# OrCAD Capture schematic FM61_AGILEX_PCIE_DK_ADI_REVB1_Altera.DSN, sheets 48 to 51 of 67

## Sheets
48 Power Inputs: size Custom
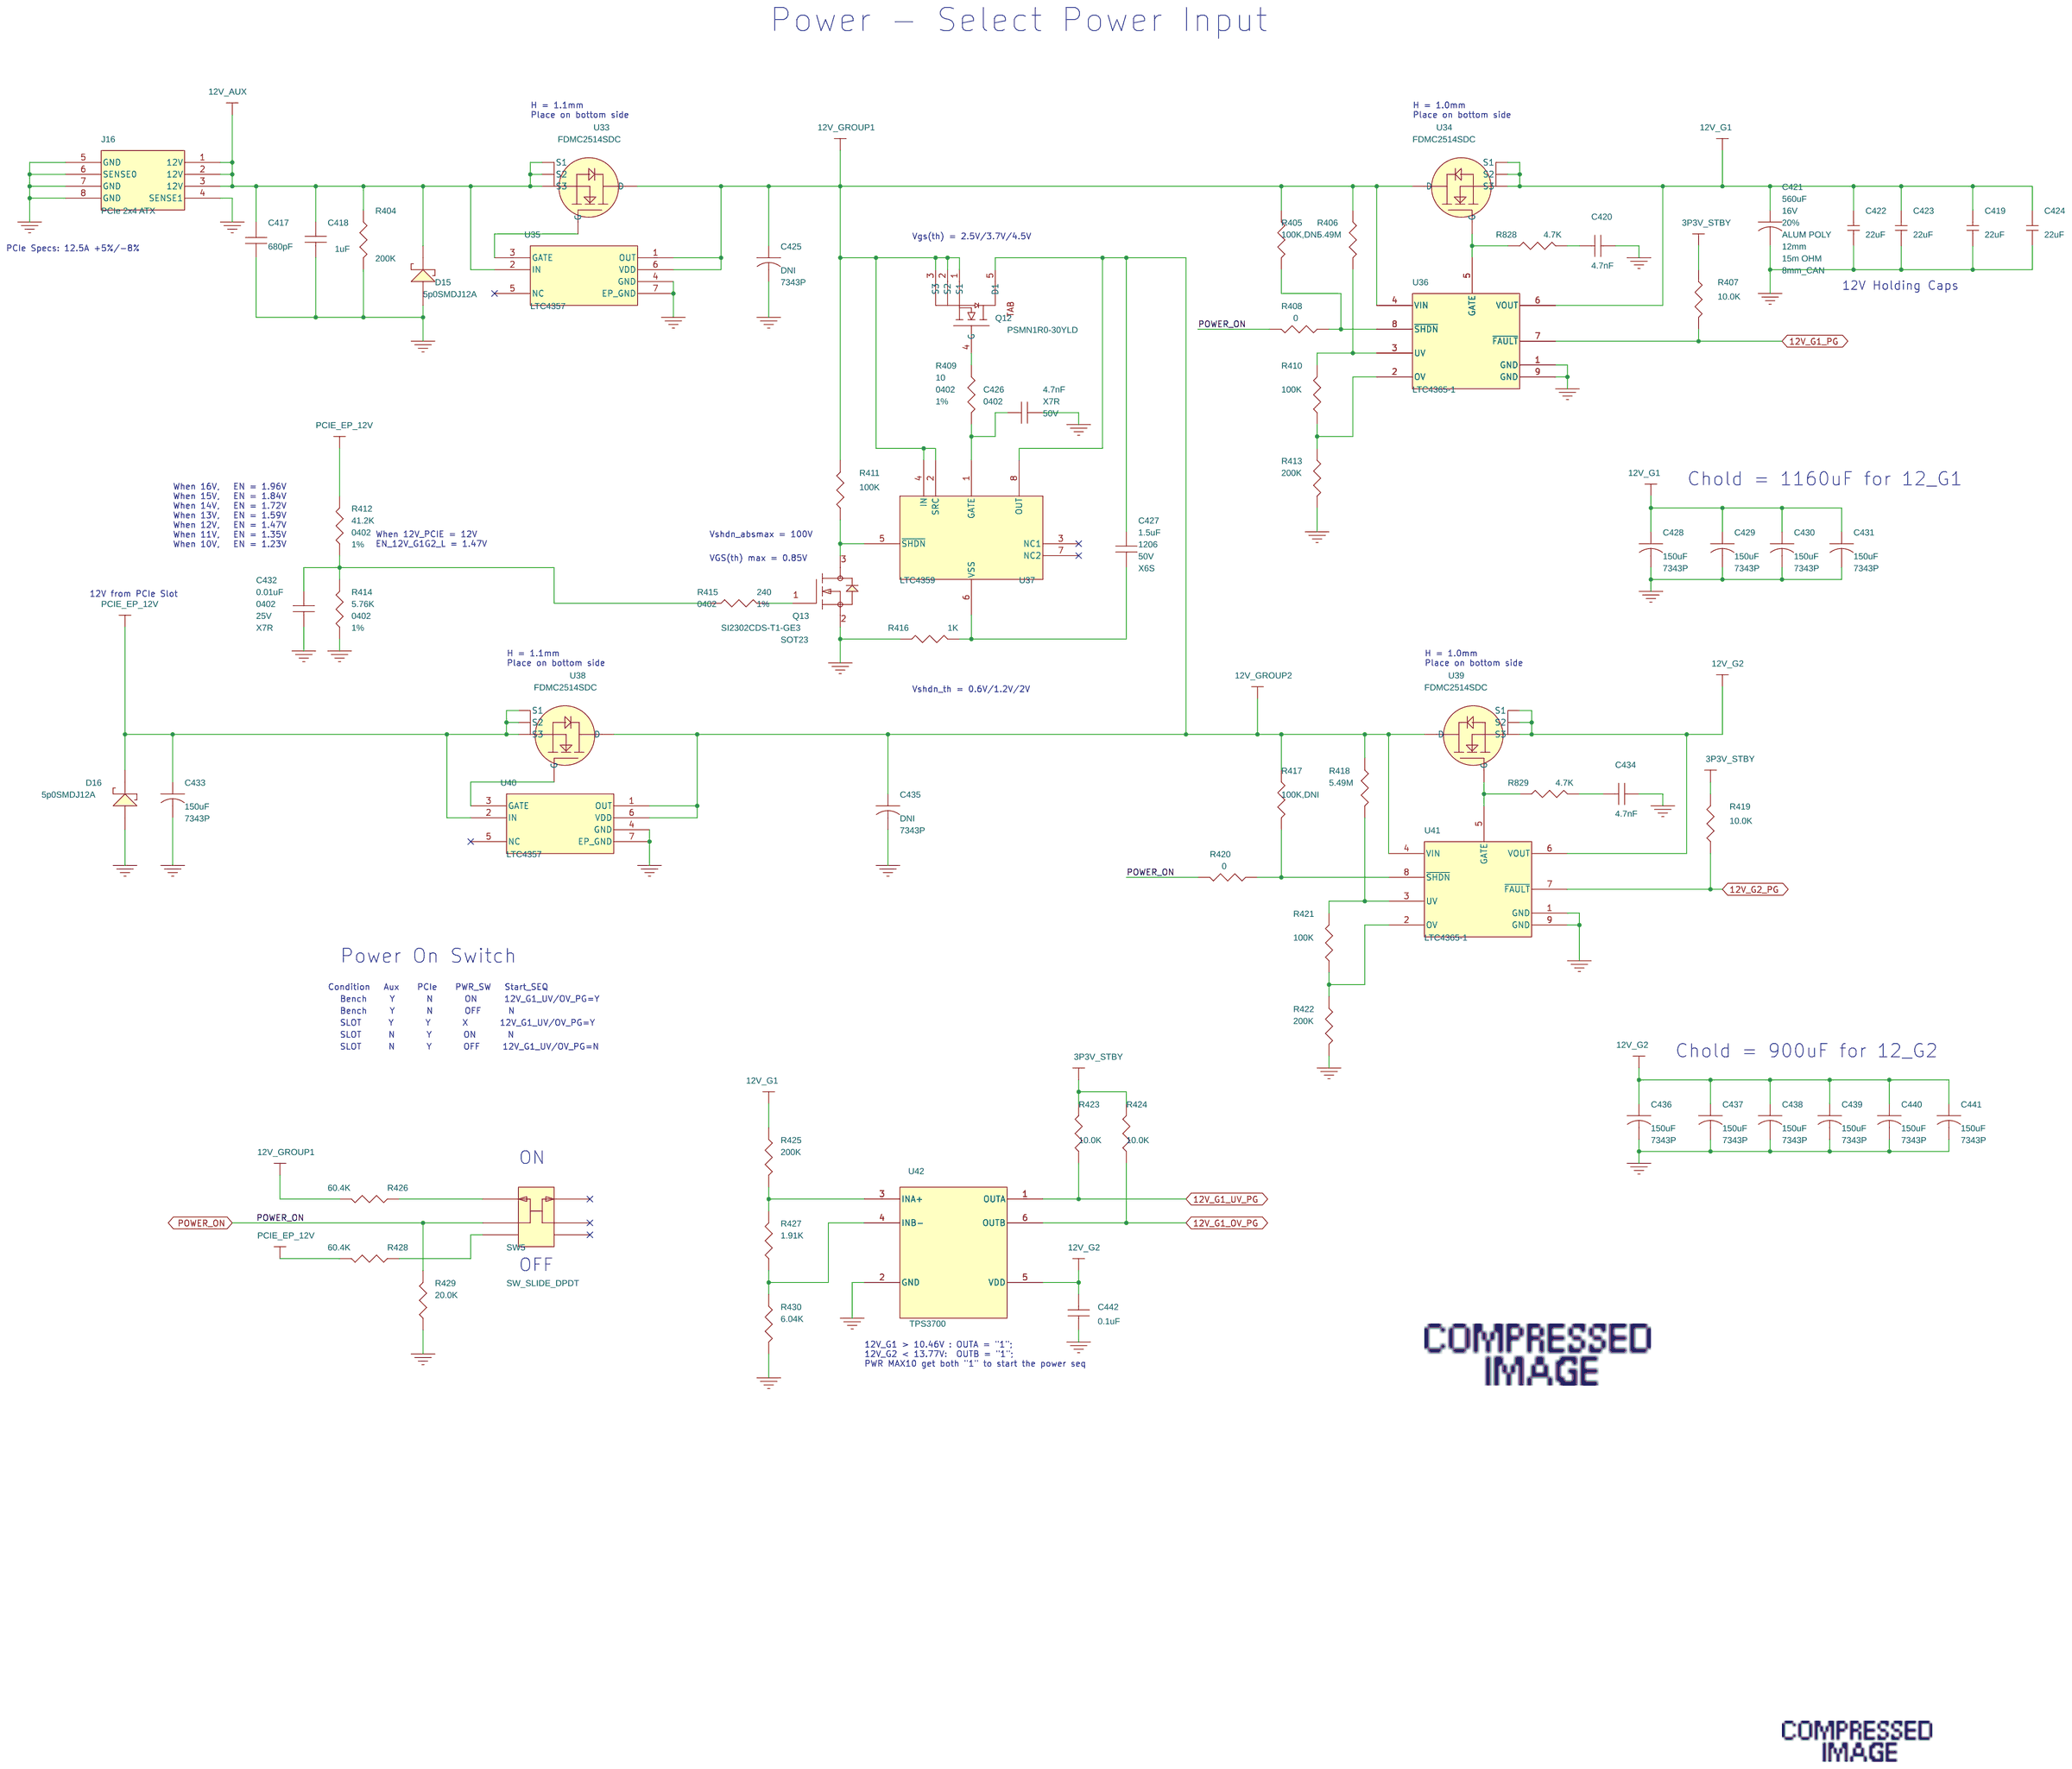
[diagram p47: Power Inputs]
49 PWR - 12V to 5V: size B
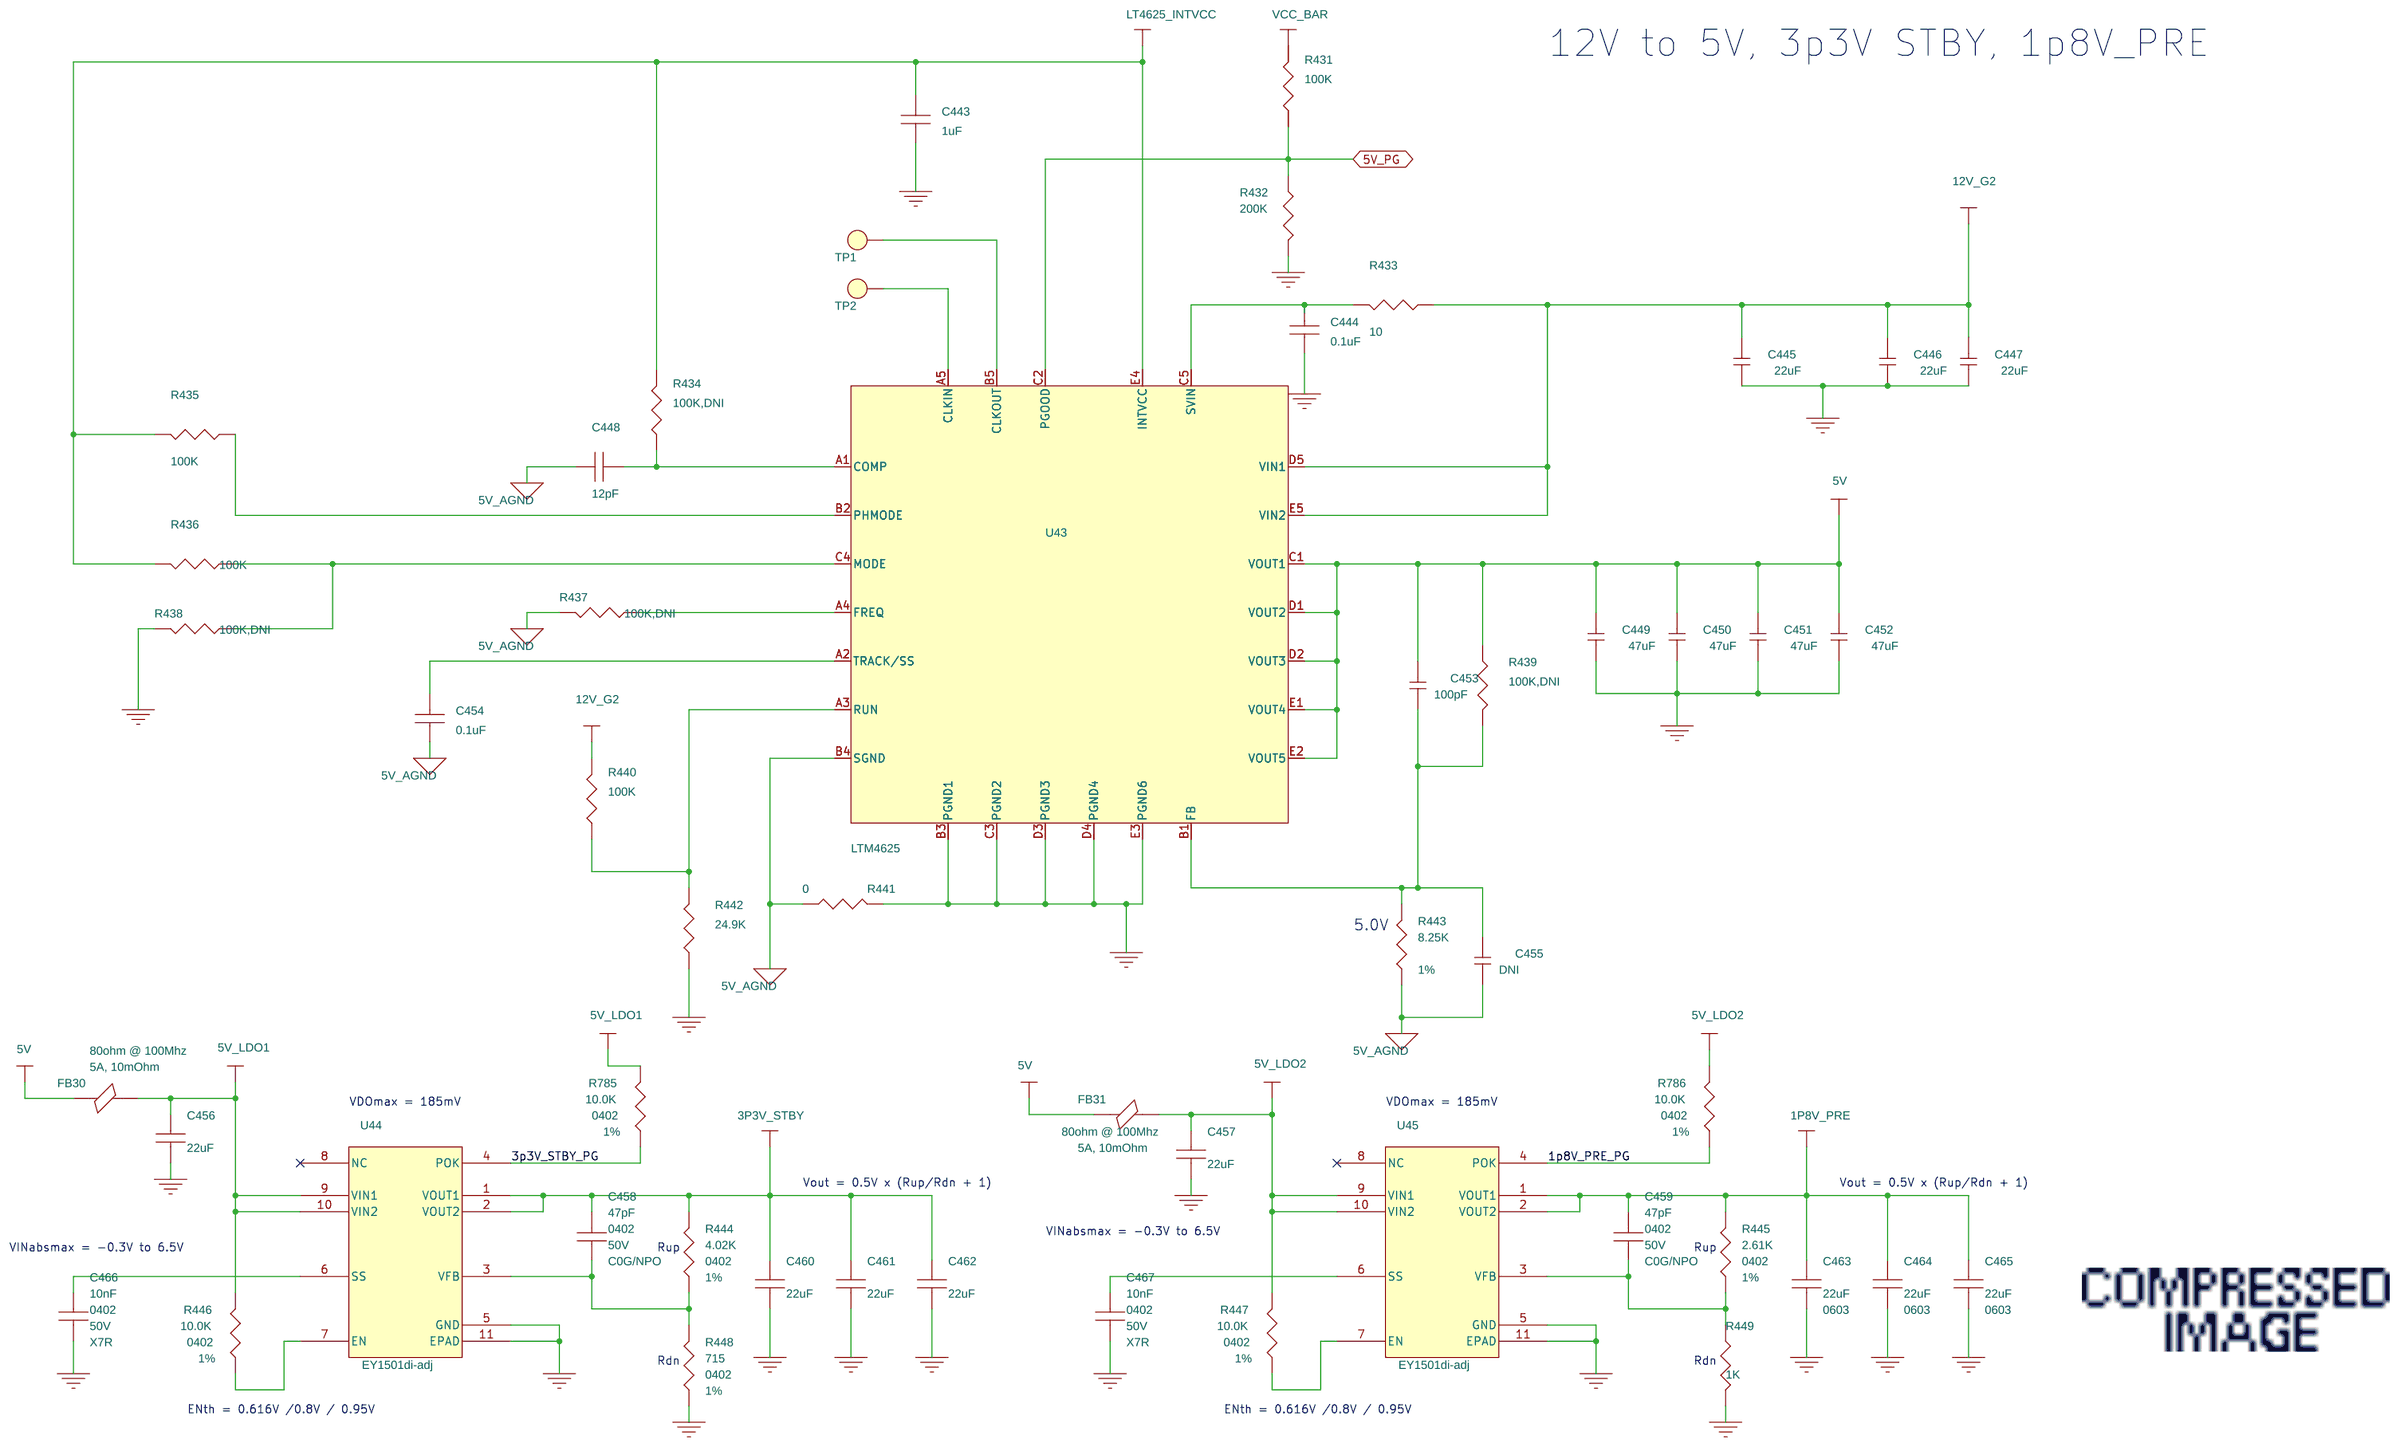
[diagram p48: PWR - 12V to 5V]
50 PWR - 12V to 3.3V: size Custom
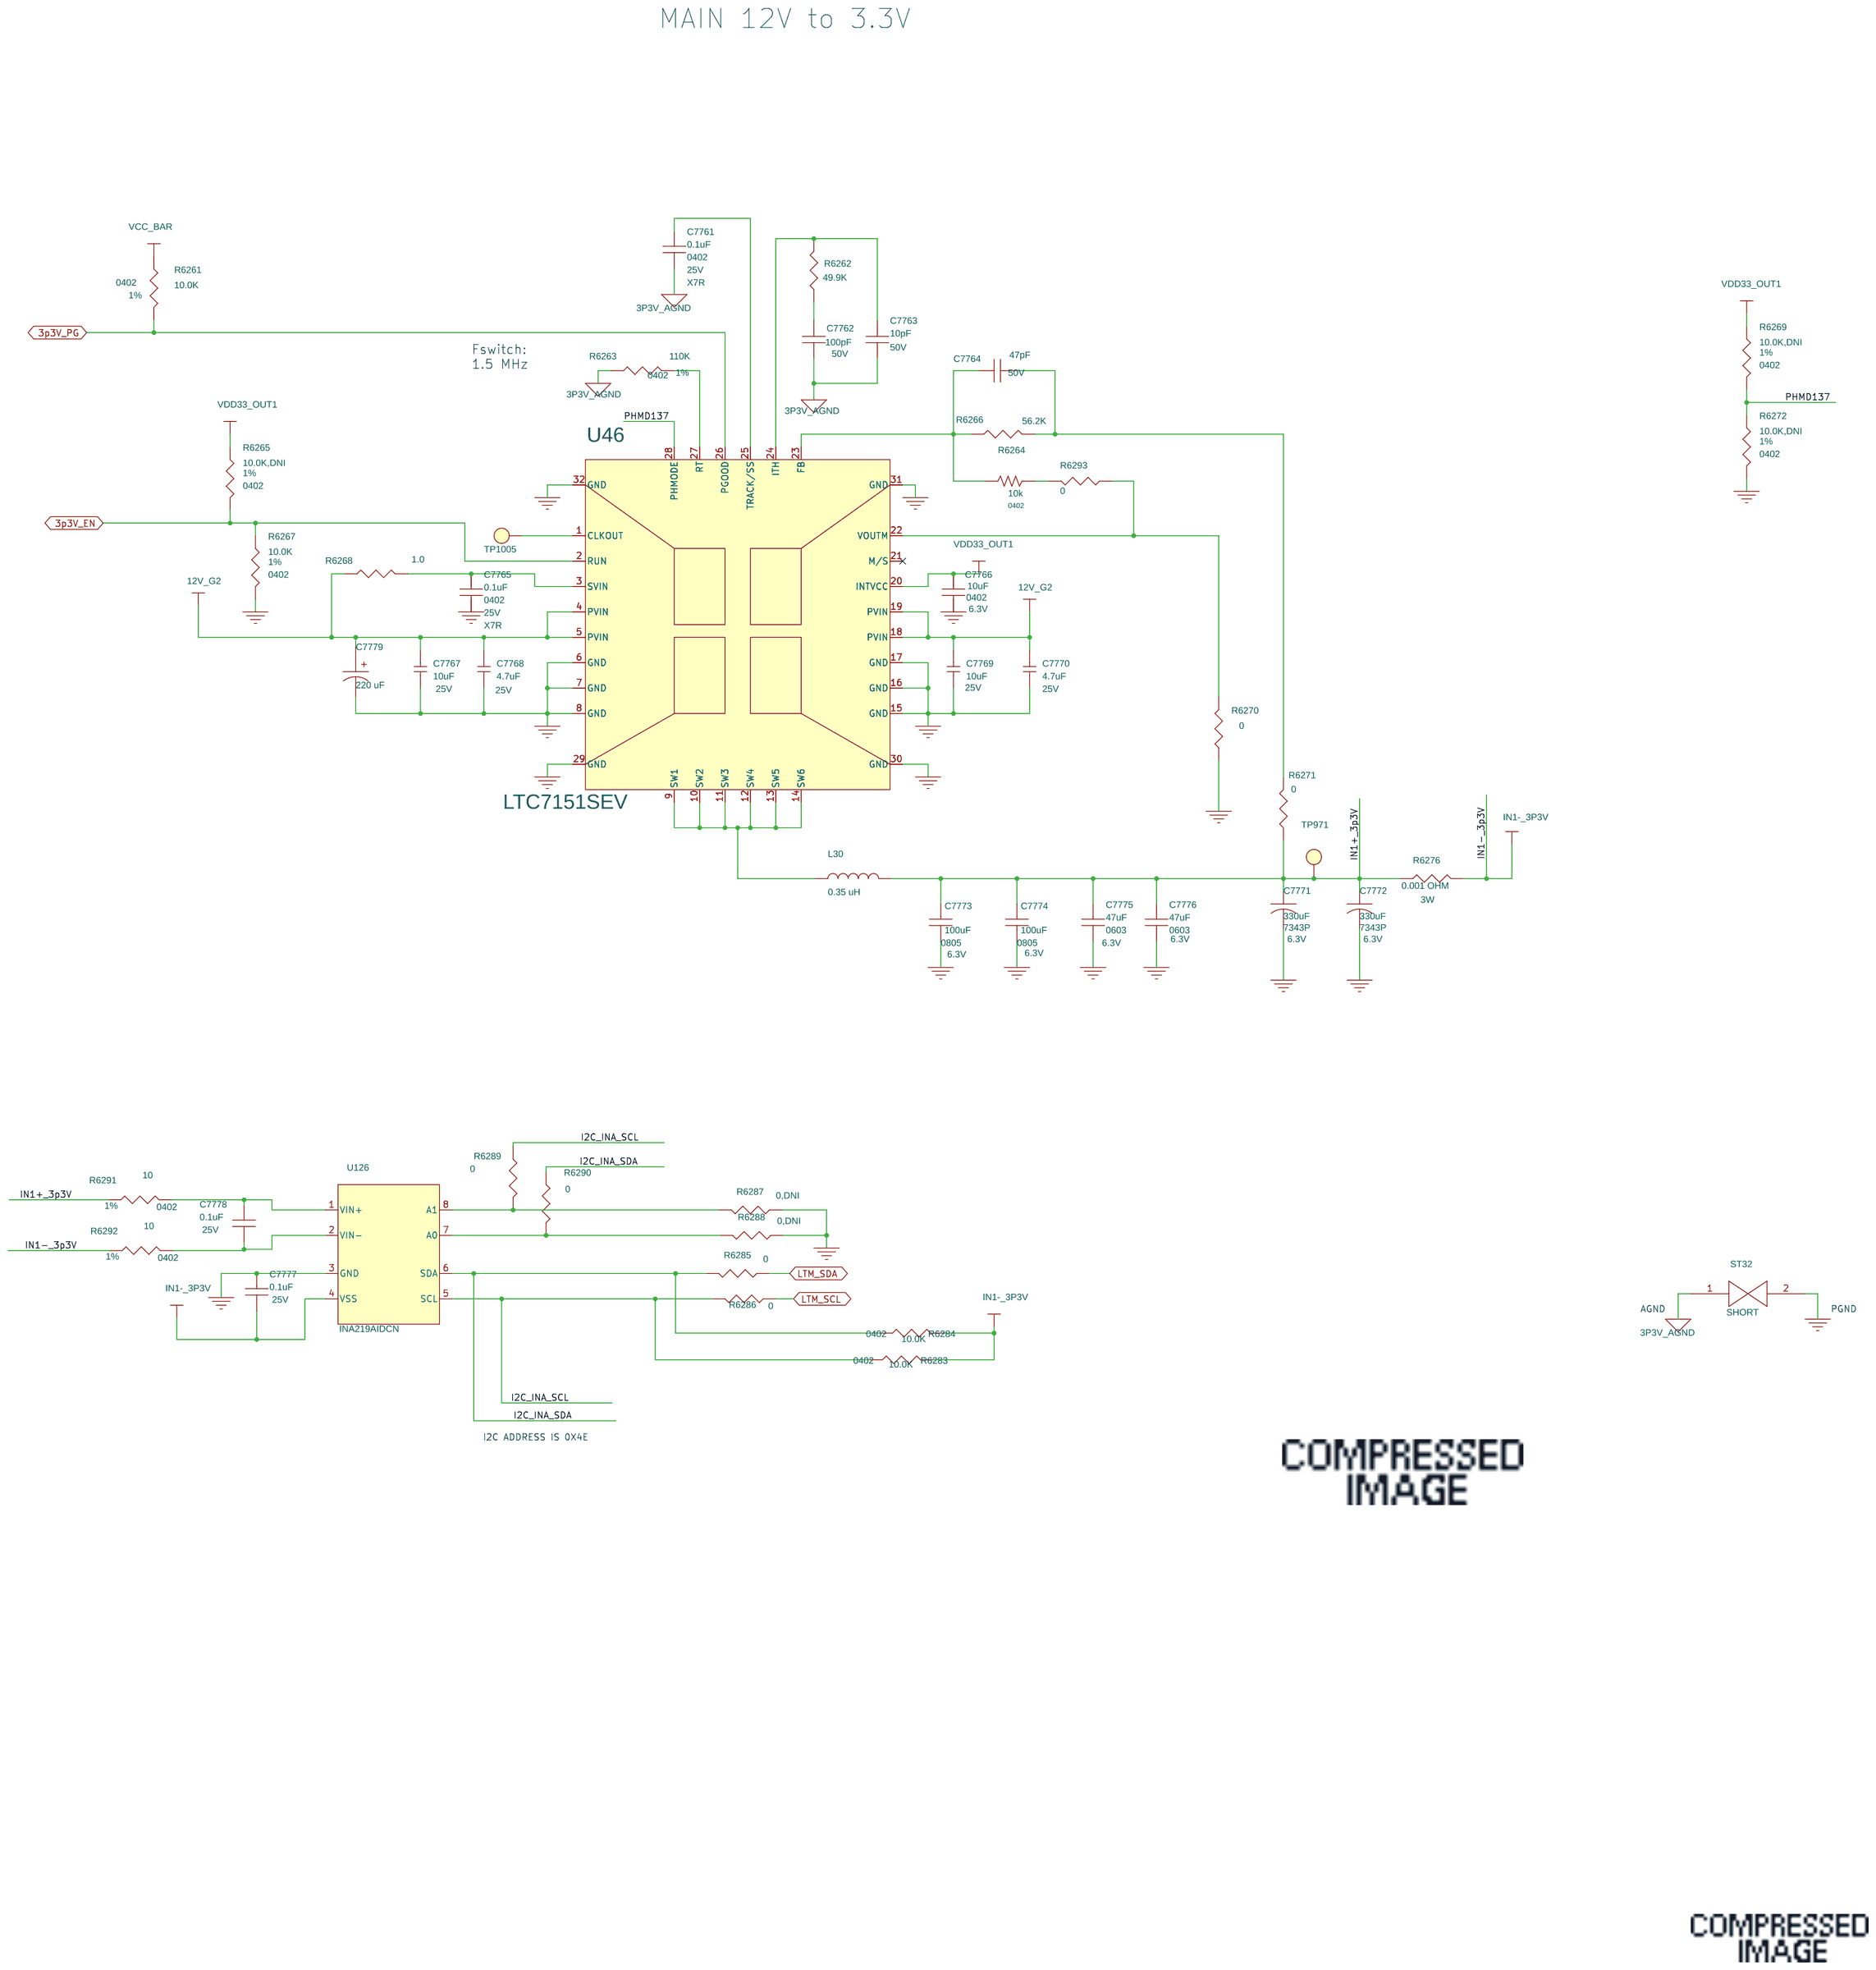
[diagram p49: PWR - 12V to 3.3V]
51 PWR - VCC -1: size Custom
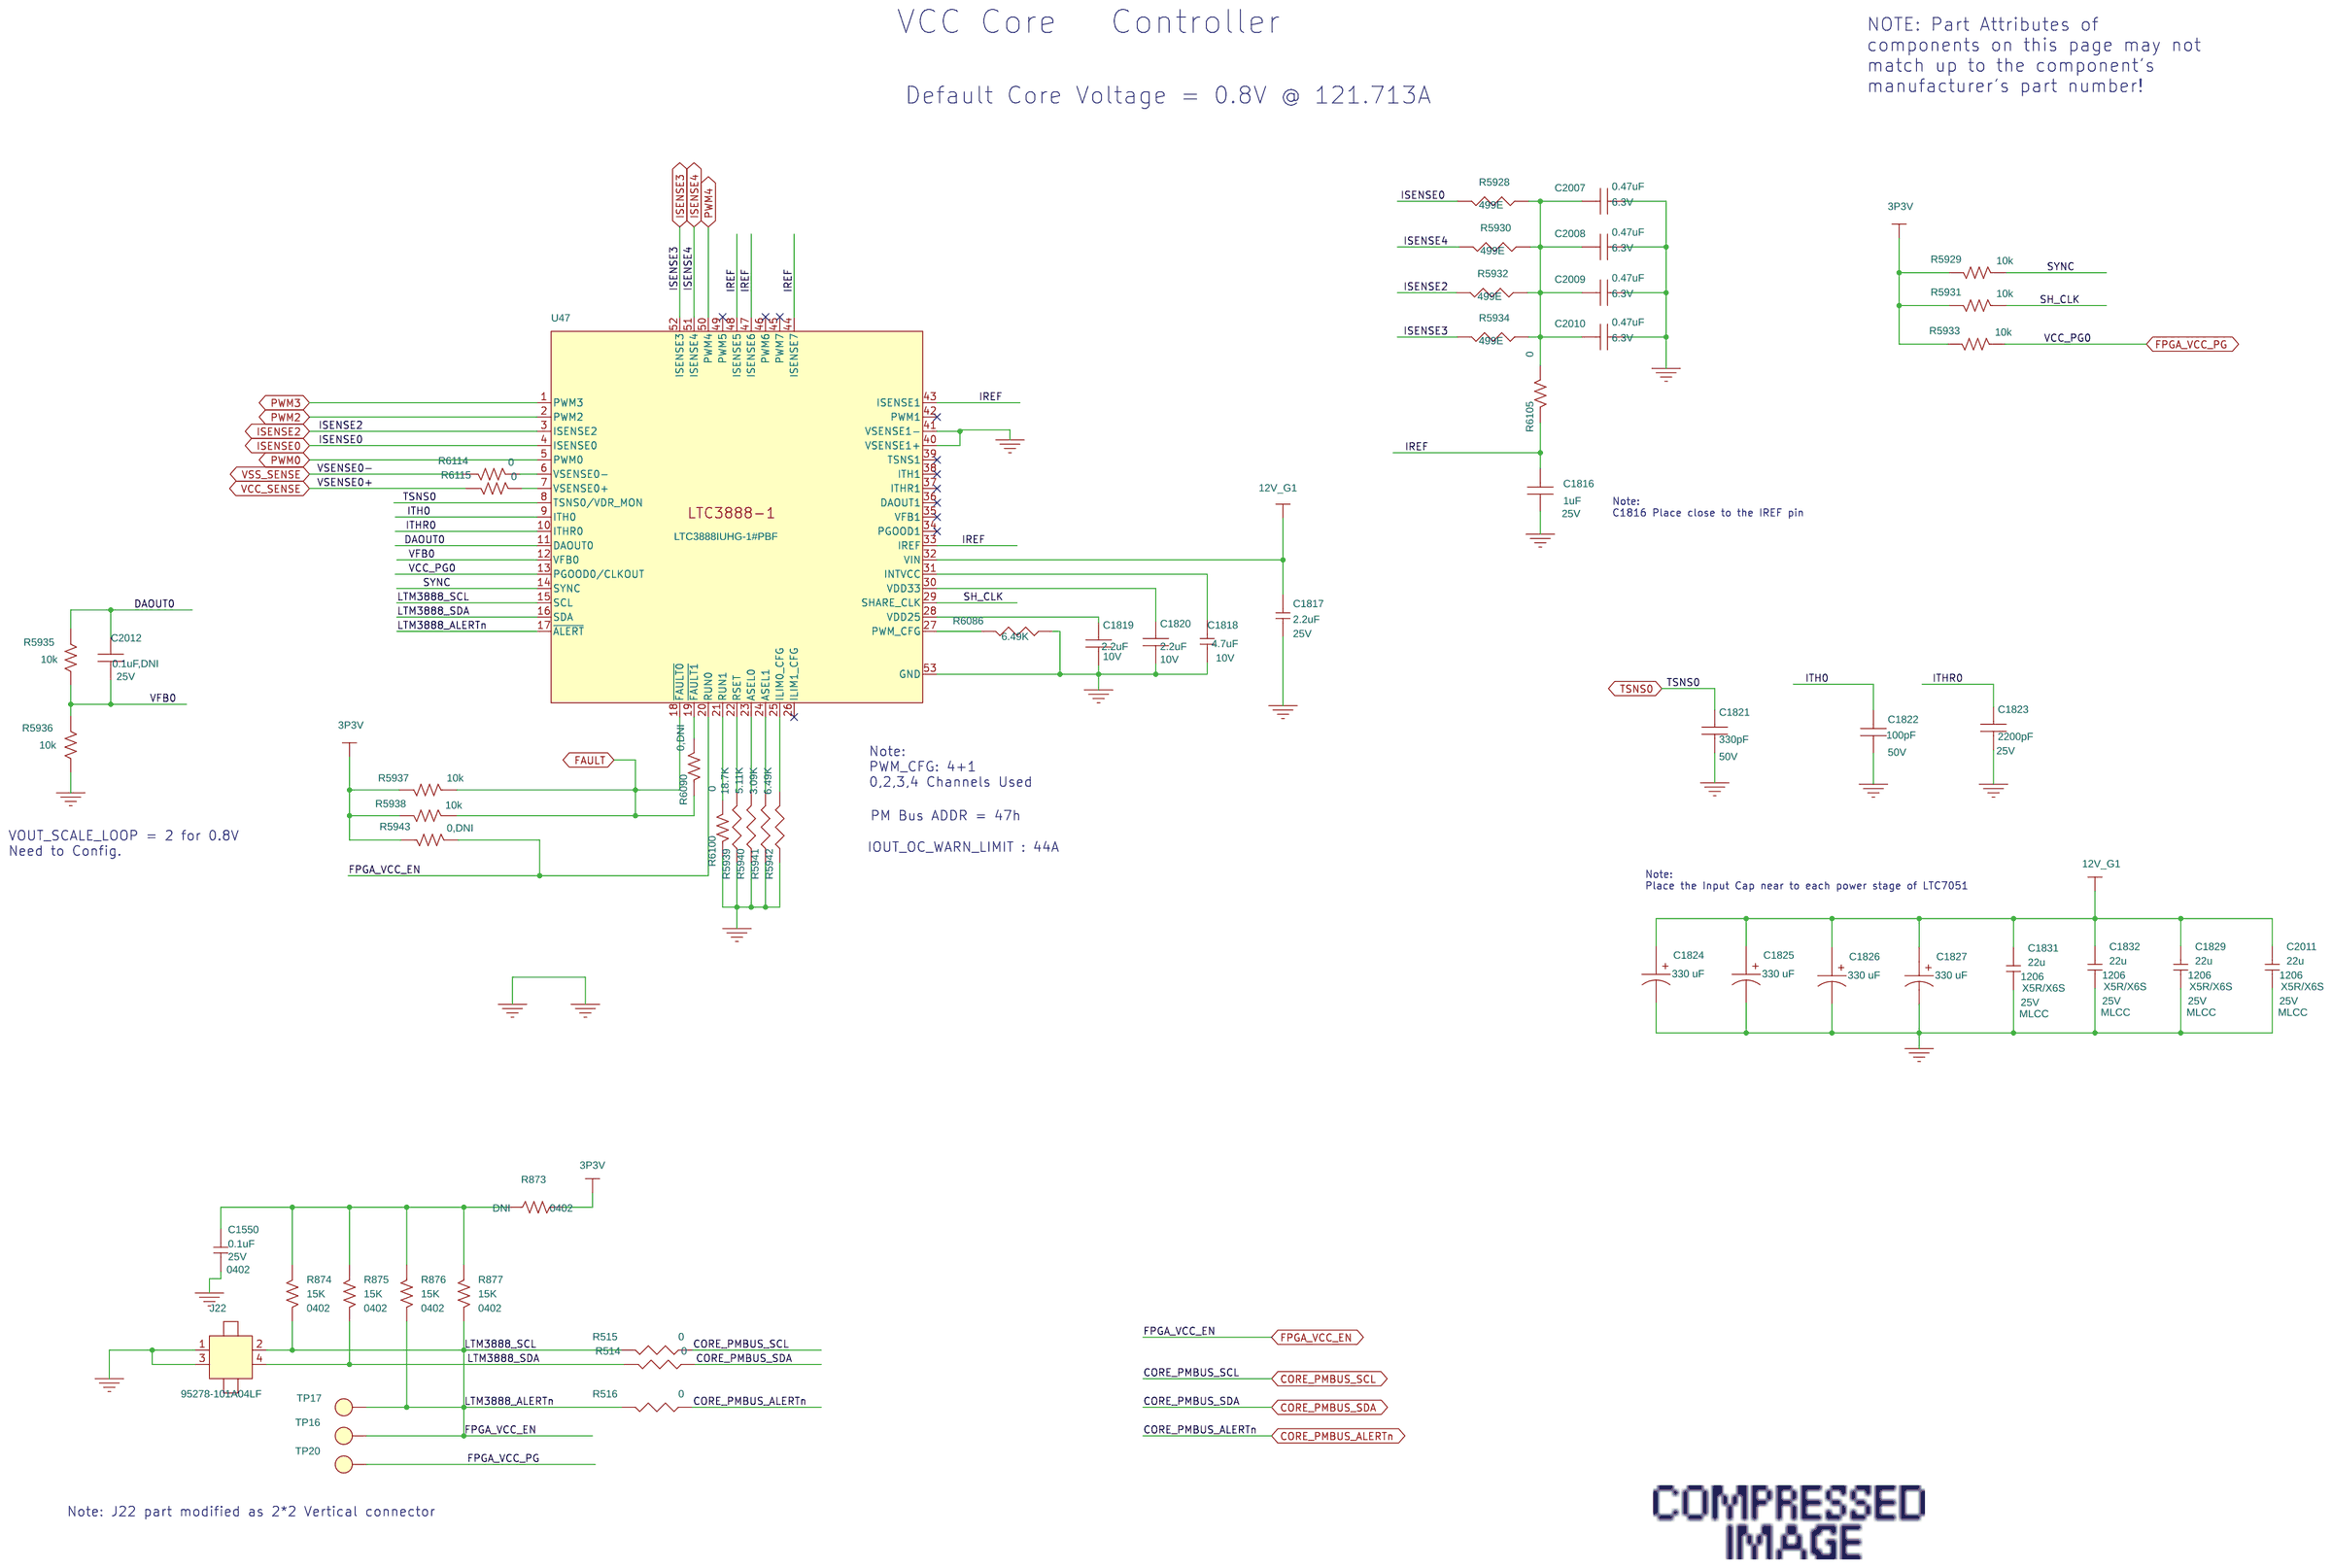
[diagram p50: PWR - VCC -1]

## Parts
sheet Power Inputs
C417  680pF  [0402]
C418  1uF  [0402]
C419  22uF  [1206]
C420  4.7nF  [0402]
C421  560uF  [8mm_CAN]
C422  22uF  [1206]
C423  22uF  [1206]
C424  22uF  [1206]
C425  DNI  [7343P]
C426  4.7nF  [0402]
C427  1.5uF  [1206]
C428  150uF  [7343P]
C429  150uF  [7343P]
C430  150uF  [7343P]
C431  150uF  [7343P]
C432  0.01uF  [0402]
C433  150uF  [7343P]
C434  4.7nF  [0402]
C435  DNI  [7343P]
C436  150uF  [7343P]
C437  150uF  [7343P]
C438  150uF  [7343P]
C439  150uF  [7343P]
C440  150uF  [7343P]
C441  150uF  [7343P]
C442  0.1uF  [0402]
D15  5p0SMDJ12A  [TVS_5p0SMDJ12A]
D16  5p0SMDJ12A  [TVS_5p0SMDJ12A]
J16  PCIe 2x4 ATX  [MLX_SD-5569_8POS_RA]
Q12  PSMN1R0-30YLD  [NFET_PSMN1R0-30YLD]
Q13  SI2302CDS-T1-GE3  [SOT23]
R404  200K  [0402]
R405  100K,DNI  [0402]
R406  5.49M  [0402]
R407  10.0K  [0402]
R408  0  [0402]
R409  10  [0402]
R410  100K  [0402]
R411  100K  [0402]
R412  41.2K  [0402]
R413  200K  [0402]
R414  5.76K  [0402]
R415  240  [0402]
R416  1K  [0402]
R417  100K,DNI  [0402]
R418  5.49M  [0402]
R419  10.0K  [0402]
R420  0  [0402]
R421  100K  [0402]
R422  200K  [0402]
R423  10.0K  [0402]
R424  10.0K  [0402]
R425  200K  [0402]
R426  60.4K  [0402]
R427  1.91K  [0402]
R428  60.4K  [0402]
R429  20.0K  [0402]
R430  6.04K  [0402]
R828  4.7K  [0402]
R829  4.7K  [0402]
SW5  SW_SLIDE_DPDT  [EG2207]
U33  FDMC2514SDC  [FDMC8878_VER2]
U34  FDMC2514SDC  [FDMC8878_VER2]
U35  LTC4357  [dfn6_epad]
U36  LTC4365-1  [DFN8-EPAD_3X2]
U37  LTC4359  [MSOP-8]
U38  FDMC2514SDC  [FDMC8878_VER2]
U39  FDMC2514SDC  [FDMC8878_VER2]
U40  LTC4357  [dfn6_epad]
U41  LTC4365-1  [DFN8-EPAD_3X2]
U42  TPS3700  [DDC]
sheet PWR - 12V to 3.3V
C7761  0.1uF  [0402]
C7762  100pF  [0402]
C7763  10pF  [0603]
C7764  47pF  [0402]
C7765  0.1uF  [0402]
C7766  10uF  [0402]
C7767  10uF  [0805]
C7768  4.7uF  [0603]
C7769  10uF  [0805]
C7770  4.7uF  [0603]
C7771  330uF  [7343P]
C7772  330uF  [7343P]
C7773  100uF  [0805]
C7774  100uF  [0805]
C7775  47uF  [0603]
C7776  47uF  [0603]
C7777  0.1uF  [0402]
C7778  0.1uF  [0402]
C7779  220 uF  [CT7361-20]
L30  0.35 uH  [IND_XGL5030]
R6261  10.0K  [0402]
R6262  49.9K  [0402]
R6263  110K  [0402]
R6264  10k  [0402]
R6265  10.0K,DNI  [0402]
R6266  56.2K  [0402]
R6267  10.0K  [0402]
R6268  1.0  [0402]
R6269  10.0K,DNI  [0402]
R6270  0  [0402]
R6271  0  [0402]
R6272  10.0K,DNI  [0402]
R6276  0.001 OHM  [RES_CSNL2512_0_005-0_006]
R6283  10.0K  [0402]
R6284  10.0K  [0402]
R6285  0  [0402]
R6286  0  [0402]
R6287  0,DNI  [0402]
R6288  0,DNI  [0402]
R6289  0  [0402]
R6290  0  [0402]
R6291  10  [0402]
R6292  10  [0402]
R6293  0  [0402]
ST32  SHORT  [SHORT]
TP971  TESTPOINT  [30MIL_TP]
TP1005  30MIL_TP  [30MIL_TP]
U46  LTC7151SEV  [LQFN_28_5MMX4MM]
U126  INA219AIDCN  [SOT23-8P]
sheet PWR - 12V to 5V
C443  1uF  [0402]
C444  0.1uF  [0402]
C445  22uF  [1206]
C446  22uF  [1206]
C447  22uF  [1206]
C448  12pF  [0402]
C449  47uF  [1206]
C450  47uF  [1206]
C451  47uF  [1206]
C452  47uF  [1206]
C453  100pF  [0402]
C454  0.1uF  [0402]
C455  DNI  [C0402]
C456  22uF  [0603]
C457  22uF  [0603]
C458  47pF  [0402]
C459  47pF  [0402]
C460  22uF  [0603]
C461  22uF  [0603]
C462  22uF  [0603]
C463  22uF  [0603]
C464  22uF  [0603]
C465  22uF  [0603]
C466  10nF  [0402]
C467  10nF  [0402]
FB30  80ohm @ 100Mhz  [0805]
FB31  80ohm @ 100Mhz  [0805]
R431  100K  [0402]
R432  200K  [0402]
R433  10  [0402]
R434  100K,DNI  [0402]
R435  100K  [0402]
R436  100K  [0402]
R437  100K,DNI  [0402]
R438  100K,DNI  [0402]
R439  100K,DNI  [0402]
R440  100K  [0402]
R441  0  [0402]
R442  24.9K  [0402]
R443  8.25K  [0402]
R444  4.02K  [0402]
R445  2.61K  [0402]
R446  10.0K  [0402]
R447  10.0K  [0402]
R448  715  [0402]
R449  1K  [0402]
R785  10.0K  [0402]
R786  10.0K  [0402]
TP1  TP, 0.016", Thru Hole  [30MIL_TP]
TP2  TP, 0.016", Thru Hole  [30MIL_TP]
U43  LTM4625  [LGA25]
U44  EY1501di-adj  [DFN-11]
U45  EY1501di-adj  [DFN-11]
sheet PWR - VCC -1
C1550  0.1uF  [CAPC1005X60L20L]
C1816  1uF  [0402]
C1817  2.2uF  [CAPC1005X60L20L]
C1818  4.7uF  [0402]
C1819  2.2uF  [0603]
C1820  2.2uF  [0603]
C1821  330pF  [0603]
C1822  100pF  [0402]
C1823  2200pF  [0402]
C1824  330 uF  [CT7343-43_CUS]
C1825  330 uF  [CT7343-43_CUS]
C1826  330 uF  [CT7343-43_CUS]
C1827  330 uF  [CT7343-43_CUS]
C1829  22u  [CAPC3216X135L50N]
C1831  22u  [CAPC3216X135L50N]
C1832  22u  [CAPC3216X135L50N]
C2007  0.47uF  [0402]
C2008  0.47uF  [0402]
C2009  0.47uF  [0402]
C2010  0.47uF  [0402]
C2011  22u  [CAPC3216X135L50N]
C2012  0.1uF,DNI  [0402]
J22  95278-101A04LF  [AMPHENOL_95278-X01X04LF]
R514  0  [0402]
R515  0  [0402]
R516  0  [0402]
R873  DNI  [RESC1005X40L20L]
R874  15K  [RESC1005X40L20L]
R875  15K  [RESC1005X40L20L]
R876  15K  [RESC1005X40L20L]
R877  15K  [RESC1005X40L20L]
R5928  499E  [0402]
R5929  10k  [0402]
R5930  499E  [0402]
R5931  10k  [0402]
R5932  499E  [0402]
R5933  10k  [0402]
R5934  499E  [0402]
R5935  10k  [0402]
R5936  10k  [0402]
R5937  10k  [0402]
R5938  10k  [0402]
R5939  18.7K  [0402]
R5940  5.11K  [0402]
R5941  3.09K  [0402]
R5942  6.49K  [0402]
R5943  0,DNI  [RESC1005X40L20L]
R6086  6.49K  [0402]
R6090  0,DNI  [RESC1005X40L20L]
R6100  0  [RESC1005X40L20L]
R6105  0  [RESC1005X40L20L]
R6114  0  [RESC1005X40L20L]
R6115  0  [RESC1005X40L20L]
TP16  TESTPOINT  [30MIL_TP]
TP17  TESTPOINT  [30MIL_TP]
TP20  TESTPOINT  [30MIL_TP]
U47  LTC3888IUHG-1#PBF  [QFN40P500X800X80-53N]

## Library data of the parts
C417 = CAP: CAP - CER, 680pF, 10%, 50V, X7R, 0402; IPN: A36096-015; Item Num: P03-15177R; LIFECYCLE_PHASE: Active; MFR_LIFECYCLE: Active; Manufacturer: Murata; Manufacturer Part Num: GRM155R71H681KA01D; Num Pins: 2; PART_SUBCLASS: CAPACITORS; RATED_VOLTAGE: 50V; RoHS Compliant: RoHS Compliant; TOLERANCE: +/-10%
C418 C443 = CAP: CAP - CER, 1UF, 25V, 10%, X5R, 0402; IPN: H29050-001; Item Num: P03-17662R; Lead Free Status: Yes; Manufacturer: TDK Electronics; Manufacturer Part Num: CGB2A1X5R1E105K033BC; Num Pins: 2; Part Class: CAPACITORS; RoHS Compliant: Yes
C419 C422-C424 C445-C447 = Cap,_NP,_1206: CAP - CER, 22UF, 25V, 10%, X5R, 1206; IPN: K28232-001; Item Num: P03-17640R; Manufacturer: Murata; Manufacturer Part Num: GRM31CR61E226KE15L
C420 C434 = CAP: CAP CER 4700PF 50V 10% X7R 0402; AGILE_LINK: http://sj-agile9app/Agile/PLMServlet?action=OpenEmailObject&classid=10000&objid=256989767; CAPACITANCE: 15000pF; IPN: K13700-001; Item Num: P03-17789R; LIFECYCLE_PHASE: Active; Lead Free Status: Lead Free; MFR_LIFECYCLE: Active; Manufacturer: Murata; Manufacturer Part Num: GRM155R71H472KA01J; Num Pins: 2; PART_SUBCLASS: CAPACITORS; RATED_VOLTAGE: 50V; RoHS Compliant: RoHS Compliant; TOLERANCE: 10%
C421 = PCAP: 560µF ±20% 16V Aluminum Polymer Capacitor Radial, Can - SMD 14 mOhm 5000 Hrs @ 105°C; AGILE_LINK: http://sj-agile9app/Agile/PLMServlet?action=OpenEmailObject&classid=10000&objid=257237054; ESR: 15m OHM; Height: 12mm; IPN: K22159-001; Item Num: P03-17987R; LIFECYCLE_PHASE: Active; Lead Free Status: Lead Free; MFR_LIFECYCLE: Active; Manufacturer: Panasonic; Manufacturer Part Num: 16SVPF560M; Num Pins: 2; PART_SUBCLASS: CAPACITORS; RATED_VOLTAGE: 16V; RoHS Compliant: RoHS Compliant; TOLERANCE: 20%; TYPE: ALUM POLY
C425 C435 = PCAP: CAP - TANT POLYMER,150UF,16V,50MOHM ESR20%, 7343*1.8MM; CAPACITANCE: 150uF; IPN: G46681-001; Item Num: P03-17713R; LIFECYCLE_PHASE: Active; Lead Free Status: Lead Free; MFR_LIFECYCLE: Active; Manufacturer: Panasonic; Manufacturer Part Num: 16TQC150MYF; Num Pins: 2; PART_SUBCLASS: CAPACITORS; RATED_VOLTAGE: 16V; RoHS Compliant: RoHS Compliant; TOLERANCE: +/-20%
C426 = CAP: CAP CER 4700PF 50V 10% X7R 0402; AGILE_LINK: http://sj-agile9app/Agile/PLMServlet?action=OpenEmailObject&classid=10000&objid=256989767; CAPACITANCE: 4700pF; IPN: K13700-001; Item Num: P03-17789R; LIFECYCLE_PHASE: Active; Lead Free Status: Lead Free; MFR_LIFECYCLE: Active; Manufacturer: Murata; Manufacturer Part Num: GRM155R71H472KA01J; Num Pins: 2; PART_SUBCLASS: CAPACITORS; RATED_VOLTAGE: 50V; RoHS Compliant: RoHS Compliant; TOLERANCE: 10%; Temperature Coefficient: X7R
C427 = CAP: CAP CER 1.5UF 50V X6S 1206; CAPACITANCE: 0.1uF; Dielectric: X6S; IPN: K19472-001; Item Num: P03-17998R; LIFECYCLE_PHASE: Active; Lead Free Status: Lead Free; Manufacturer: Murata; Manufacturer Part Num: GRT31CC81H155KE01L; Num Pins: 2; Part Class: CAPACITORS; RATED_VOLTAGE: 50V; RoHS Compliant: RoHS Compliant; Tolerance: 10%
C428-C431 C433 C436-C441 = PCAP: CAP - TANT POLYMER,150UF,16V,50MOHM ESR20%, 7343*1.8MM; IPN: G46681-001; Item Num: P03-17713R; LIFECYCLE_PHASE: Active; Lead Free Status: Lead Free; MFR_LIFECYCLE: Active; Manufacturer: Panasonic; Manufacturer Part Num: 16TQC150MYF; Num Pins: 2; PART_SUBCLASS: CAPACITORS; RATED_VOLTAGE: 16V; RoHS Compliant: RoHS Compliant; TOLERANCE: +/-20%
C432 = CAP: CAP CER 10000PF 25V X7R 0402; AGILE_LINK: http://sj-agile9app/Agile/PLMServlet?action=OpenEmailObject&classid=10000&objid=242850622; IPN: A36096-008; Item Num: P03-17012R; LIFECYCLE_PHASE: Active; MFR_LIFECYCLE: Active; Manufacturer: Murata; Manufacturer Part Num: GRM155R71E103KA01D; Num Pins: 2; PACKAGING: Tape & Reel (TR); PART_SUBCLASS: CAPACITORS; RATED_VOLTAGE: 25V; RoHS Compliant: RoHS Compliant; TOLERANCE: 10%; Temperature Coefficient: X7R
C442 C444 C454 = CAP: CAP CER 0.1UF 25V 20% X7R 0402; AGILE_LINK: http://sj-agile9app/Agile/PLMServlet?action=OpenEmailObject&classid=10000&objid=213459527; IPN: K13660-001; Item Num: P03-17618R; LIFECYCLE_PHASE: Active; Lead Free Status: Lead Free; MFR_LIFECYCLE: Active; Manufacturer: TDK Electronics; Manufacturer Part Num: C1005X7R1E104M; Num Pins: 2; PART_SUBCLASS: CAPACITORS; Part Class: CAPACITORS; RATED_VOLTAGE: 25V; RoHS Compliant: RoHS Compliant; TOLERANCE: +80%/-20%
D15 D16 = TVS_5p0SMDJ12A: TVS DIODE 12VWM 19.9VC SMD; IPN: J31279-001; Item Num: P08-20862R; Manufacturer: Littelfuse Inc.; Manufacturer Part Num: 5.0SMDJ12A
J16 = 2X4_PCIE_ATX_1: CONN - PCIE ATX, 8POS HEADER, 4.2MM, R/A; IPN: K11298-001; Item Num: P23-38586R; Manufacturer: Zhongxlang Electron Science Co. LTD; Manufacturer Part Num: 45586-0005
Q12 = PSMN1R0-30YLD_0: MOSFET, N-Channel, 30V, 1mOhm, 300A; IPN: K21466-001; Item Num: P18-31489R; Manufacturer: Nexperia USA Inc.
Q13 = PWRMOSFET_EN_GSD_1: MOSFET N-CH 20V 2.6A SOT23-3; IPN: E87223-001; Item Num: P18-31488R; Manufacturer: Vishay Siliconix
R404 R413 R422 R432 = RES: RES - 200K OHM, 1/16W, 1%, 0402 SMD; IPN: A93548-186; Item Num: P02-15992R; Manufacturer: Panasonic; Manufacturer Part Num: ERJ-2RKF2003X; Package: SMD; Part Class: RESISTORS; Type: Resistor
R405 R417 = RESISTOR: RES,100K OHMS,1.0%,1/16W,0402; IPN: E86804-001; Item Num: P02-11386R; Lead Free Status: No; Manufacturer: Panasonic; Manufacturer Part Num: ERJ-2RKF1003X; Num Pins: 2; POWER: 1/16W; Part Class: Resistors; Price: 0; RESISTANCE: 100K; RoHS Compliant: Yes; TOLERANCE: +/-1%
R406 R418 = RESISTOR: RES - 5.49M OHM, 1/16W, 1%, 0402 SMD; IPN: K16257-001; Item Num: P02-17605R; Lead Free Status: Yes; Manufacturer: Vishay; Manufacturer Part Num: CRCW04025M49FKED; Num Pins: 2; Part Class: Resistors
R407 R419 R423 R424 = RESISTOR: RES,10.0K OHMS,1.0%,1/16W, 0402; AGILE_LINK: http://sj-agile9app/Agile/PLMServlet?action=OpenEmailObject&classid=10000&objid=146548997; IPN: A93548-034; Item Num: P02-11364R; LIFECYCLE_PHASE: Active; Lead Free Status: No; MFR_LIFECYCLE: Active; Manufacturer: Panasonic; Manufacturer Part Num: ERJ-2RKF1002X; Num Pins: 2; PART_SUBCLASS: RESISTORS; POWER: 1/16W; RoHS Compliant: Yes; TOLERANCE: +/-1%
R408 R420 R514-R516 = RES_0_OHM_5%_1_16W_0402_SMD: IPN: H30887-001
R409 R433 R6291 R6292 = RESISTOR: RES, 10 OHMS, 1.0%, 1/10W, 0402; AGILE_LINK: http://sj-agile9app/Agile/PLMServlet?action=OpenEmailObject&classid=10000&objid=146932246; IPN: A80345-001; Item Num: P02-16268R; LIFECYCLE_PHASE: Active; MFR_LIFECYCLE: Active; Manufacturer: Panasonic; Manufacturer Part Num: ERJ-2RKF10R0X; Num Pins: 2; PART_SUBCLASS: RESISTORS; POWER: 1/16W; RoHS Compliant: RoHS Compliant; TOLERANCE: 1%
R410 R411 R421 = RESISTOR: RES,100K OHMS,1.0%,1/16W,0402; IPN: E86804-001; Item Num: P02-11386R; Lead Free Status: No; Manufacturer: Panasonic; Manufacturer Part Num: ERJ-2RKF1003X; Num Pins: 2; POWER: 1/16W; Part Class: Resistors; Price: 0; RoHS Compliant: Yes; TOLERANCE: +/-1%
R412 = RESISTOR: RES SMD 41.2K OHM 1% 1/10W 0402; AGILE_LINK: http://sj-agile9app/Agile/PLMServlet?action=OpenEmailObject&classid=10000&objid=146548997; IPN: K16280-001; Item Num: P02-15507R; LIFECYCLE_PHASE: Active; Lead Free Status: No; MFR_LIFECYCLE: Active; Manufacturer: Panasonic; Manufacturer Part Num: ERJ-2RKF4122X; Num Pins: 2; PART_SUBCLASS: RESISTORS; POWER: 1/10W; RoHS Compliant: Yes; TOLERANCE: 1%
R414 = RESISTOR: RES SMD 5.76K OHM 1% 1/10W 0402; AGILE_LINK: http://sj-agile9app/Agile/PLMServlet?action=OpenEmailObject&classid=10000&objid=146548997; IPN: K15735-001; Item Num: P02-15108R; LIFECYCLE_PHASE: Active; Lead Free Status: No; MFR_LIFECYCLE: Active; Manufacturer: Panasonic; Manufacturer Part Num: ERJ-2RKF5761X; Num Pins: 2; PART_SUBCLASS: RESISTORS; POWER: 1/10W; RoHS Compliant: Yes; TOLERANCE: 1%
R415 = RESISTOR: RES - 240 OHM, 1/16W, 1%, 0402 SMD; Altera Part No.: P02-15995R; IPN: K15783-001; Item Num: P02-15995R; Lead Free Status: No; Manufacturer: Panasonic; Manufacturer Part Num: ERJ-2RKF2400X; Num Pins: 2; Part Class: RESISTORS; Price: 0; RoHS Compliant: Yes; Tolerance: 1%
R416 R449 = RESISTOR: RES,1.00K OHMS,1.0%,1/16W,0402; IPN: G60609-021; Item Num: P02-11372R; Lead Free Status: No; Manufacturer: Panasonic; Manufacturer Part Num: ERJ-2RKF1001X; Num Pins: 2; Part Class: Resistors
R425 = RESISTOR: RES - 200K OHM, 1/16W, 1%, 0402 SMD; IPN: A93548-186; Item Num: P02-15992R; Manufacturer: Panasonic; Manufacturer Part Num: ERJ-2RKF2003X; Tolerance: +/-1%
R426 R428 = RESISTOR: RES,60.4K,1/16W,1%,0402,SMD; IPN: K15653-001; Item Num: P02-15467R; Manufacturer: Rohm; Manufacturer Part Num: MCR01MZPF6042
R427 = RESISTOR: RES - 1.91K OHM, 1%, 1/10W 0402 SMD; IPN: D89469-001; Item Num: P02-17528R; Manufacturer: Panasonic; Manufacturer Part Num: ERJ-2RKF1911X; Tolerance: +/-1%
R429 = RESISTOR: RES 20.0K OHM 1/16W 1% 0402 SMD; IPN: A78608-001; Item Num: P02-14071R; Lead Free Status: Yes; Manufacturer: Panasonic; Manufacturer Part Num: ERJ-2RKF2002X; Num Pins: 2; Part Class: RESISTORS; RoHS Compliant: Yes
R430 = RESISTOR: RES 6.04K OHM 1/16W 1% 0402 SMD; IPN: A93548-197; Item Num: P02-17233R; Manufacturer: Vishay; Manufacturer Part Num: CRCW04026K04FKED; Tolerance: +/-1%
R828 R829 = RESISTOR: RES 4.7K OHM 1/16W 5% 0402 SMD; IPN: H30885-001; Item Num: P02-14032R; Lead Free Status: No; Manufacturer: Panasonic; Manufacturer Part Num: ERJ-2GEJ472X; Manufacturer's Part No.: ERJ-2GEJ472X; Num Pins: 2; Part Class: RESISTORS; Price: 0; RoHS Compliant: Yes
SW5 = SW_SLIDE_DPDT: SWITCH - SLIDE DPDT, 30V, 0.2AMP, Vertical; IPN: J42686-001; Item Num: P11-24518R; Manufacturer: E-SWITCH
U33 U34 U38 U39 = FDMC8878_VER2: MOSFET N-CHANNEL DUAL COOL PWR TRENCH 40A 25V 3.5mOHM; IPN: K14521-001; Item Num: P18-31451R; Manufacturer: Fairchild Semiconductor
U35 U40 = LTC4357: IC - POSITIVE HIGH VOLTAGE IDEAL DIODE CONTROLLER, VIN 9V-80V, 6-LEAD DFN; AGILE_LINK: http://sj-agile9app/Agile/PLMServlet?action=OpenEmailObject&classid=10000&objid=259478351; IPN: K64810-001; Item Num: P01-14904R; LIFECYCLE_PHASE: Preliminary; Lead Free Status: Lead Free; MFR_LIFECYCLE: Active; Manufacturer: Linear Technology; Manufacturer Part Num: LTC4357IDCB#TRMPBF; Num Pins: 7; PART_SUBCLASS: ICS; RoHS Compliant: RoHS Compliant
U36 U41 = LTC4365_DFN: IC,UV,OV,SUPPLY PROTECTION,,-1,3X2X0.75MM,-40C-125C; IPN: K13853-001; Item Num: P01-17989R; LIFECYCLE_PHASE: Active; Lead Free Status: Lead Free; MFR_LIFECYCLE: Active; Manufacturer: Linear Technology; Manufacturer Part Num: LTC4365CDDB-1#TRMPBF; Num Pins: 9; PART_SUBCLASS: ICS; RoHS Compliant: RoHS Compliant
U37 = LTC4359: IC - Ideal Diode Controller with Reverse Input Protection; IPN: K22140-001; Item Num: P01-18231R; Manufacturer: Linear Technology; Manufacturer Part Num: LTC4359IMS8#PBF
U42 = TPS3700: IPN: J43211-001
C7761 C7765 C7777 C7778 = CAP: CAP CER 0.1UF 25V 20% X7R 0402; Dielectric: X7R; IPN: A36096-112; Item Num: A36096-112; LIFECYCLE_PHASE: Active; Lead Free Status: Lead Free; Manufacturer: Murata; Manufacturer Part Num: GRM155R71E104KE14D; Num Pins: 2; Part Class: CAPACITORS; RATED_VOLTAGE: 25V; RoHS Compliant: RoHS Compliant; Tolerance: 10%; Voltage: 25V
C7762 = CAP: CAPC,C0G,0402,100.000PF,50.000V,+/-5%; Dielectric: X7R; IPN: A36095-026; IPN No: A36095-026; Item Num: P03-XXXXXR; LIFECYCLE_PHASE: Active; Lead Free Status: Lead Free; Manufacturer: AVX; Manufacturer Part Num: UMK105CG101JV-F; Num Pins: 2; Part Class: CAPACITORS; RATED_VOLTAGE: 50V; RoHS Compliant: RoHS Compliant; Tolerance: 10%; Working Voltage: 50V
C7763 = CAP_NP: CAP,CER,10PF,50V,5%,X7R 0603; IPN: G60315-001; Manufacturer: Murata; Manufacturer Part Num: GRM1885C1H100JA01D; RATED_VOLTAGE: 50V; Voltage: 50V
C7764 = CAP: CAP,0402,47PF,50V,DC,5%; IPN: A78596-001; Item Num: A78596-001; Manufacturer: Panasonic; Manufacturer Part Num: ECJ-0EC1H470J; RATED_VOLTAGE: 50V
C7766 = CAP: CAP CER 10UF 6.3V X5R 0402; IPN: K46607-001; Item Num: K46607-001; Lead Free Status: Lead Free; Manufacturer: Murata Electronics North America; Manufacturer Part Num: GRJ155R60J106ME11D; Num Pins: 2; PART_SUBCLASS: CAPACITORS; Part Class: CAPACITORS; RATED_VOLTAGE: 6.3V; RoHS Compliant: RoHS Compliant; Temperature Coefficient: X5R; Voltage: 6.3V
C7767 C7769 = Cap,_NP,_1206: CAPC,0805,X5R,10UF,25V,+/-10%; Dielectric: X5R; IPN: G39150-001; Item Num: G39150-001; Manufacturer: Yageo; Manufacturer Part Num: GRM21BR61E106K; PART_NUMBER: GRM21BR61E106K; Part Number: GRM21BR61E106K; TOLERANCE: ±10%; Voltage: 25V
C7768 C7770 = Cap,_NP,_1206: CAPC,X5R,0603,4.7UF,25V,+/-10%; Agile Part Number: P03-15063R; Dielectric: X5R; IPN: K13740-001; Item Num: K13740-001; Manufacturer: Murata; Manufacturer Part Num: GRM188R61E475KE11D; Part Number: GRM188R61E475KE11D; TOLERANCE: ±10%; Voltage: 25V
C7771 C7772 = PCAP: CAP OXI LOESR 330UF 6.3V 20%SMD; IPN: E85955-001; Item Num: P03-17713R; LIFECYCLE_PHASE: Active; Lead Free Status: Lead Free; MFR_LIFECYCLE: Active; Manufacturer: Panasonic; Manufacturer Part Num: NOSE337M006R0080; Num Pins: 2; PART_SUBCLASS: CAPACITORS; RATED_VOLTAGE: 16V; RoHS Compliant: RoHS Compliant; TOLERANCE: +/-20%; Voltage: 6.3V
C7773 C7774 = CAP: CAP CER 100UF 6.3V X5R 0805; IPN: K32109-001; Item Num: K32109-001; Lead Free Status: Lead Free; Manufacturer: Murata Electronics North America; Manufacturer Part Num: GRM21BR60J107ME15L; Num Pins: 2; PART_SUBCLASS: CAPACITORS; Part Class: CAPACITORS; RATED_VOLTAGE: 6.3V; RoHS Compliant: RoHS Compliant; Temperature Coefficient: X5R; Voltage: 6.3V
C7775 C7776 = CAP: CAP CER 47UF 6.3V X5R 0603; IPN: K31624-001; Item Num: K31624-001; MFR_LIFECYCLE: Active; Manufacturer: Murata Electronics North America; Manufacturer Part Num: GRM188R60J476ME15D; Num Pins: 2; PART_SUBCLASS: CAPACITORS; RATED_VOLTAGE: 6.3V; RoHS Compliant: RoHS Compliant; TOLERANCE: 20%; Voltage: 6.3V
C7779 = TCN4227M025R0100: IPN: M75353-001
L30 = XGL5030-351MEC: IND,0.35UH,24.5A,2.2MOHM,5.48MM*5.28MM,SM; IPN: M85044-001; Item Num: M85044-001
R6261 R6265 R6267 R6269 R6272 R6283 R6284 = RESISTOR: RES,10.0K OHMS,1.0%,1/16W, 0402; AGILE_LINK: http://sj-agile9app/Agile/PLMServlet?action=OpenEmailObject&classid=10000&objid=146548997; IPN: A93548-034; Item Num: A93548-034; LIFECYCLE_PHASE: Active; Lead Free Status: No; MFR_LIFECYCLE: Active; Manufacturer: Panasonic; Manufacturer Part Num: ERJ-2RKF1002X; Num Pins: 2; PART_SUBCLASS: RESISTORS; POWER: 1/16W; RESISTANCE: 10K; RoHS Compliant: Yes; TOLERANCE: 1%
R6262 = RESISTOR: RES SMD 49.9KOHM 0.1% 1/16W 0402; IPN: C79651-037; Item Num: P02-17979R; Manufacturer: Panasonic; Manufacturer Part Num: ERA-2AEB4992X
R6263 = RESISTOR: RESD,0402,1%,1/16W,110K; IPN: E30631-001; Item Num: E30631-001; Lead Free Status: No; Manufacturer: CYNTEC CO.LTD; Manufacturer Part Num: RR05105-114-FN; Num Pins: 2; Part Class: RESISTORS; Price: 0; RoHS Compliant: Yes; Tolerance: 1%
R6264 = Resistor,_0402: RES 10K OHM 1/16W 5% 0402 SMD; Agile Part Number: P02-17688R; IPN: K28115-001; Item Num: K28115-001; Manufacturer: Panasonic; Manufacturer Part Num: ERJ-2RKF1002X; Part Number: ERJ-2RKF1002X; Power: 1/16W; TOLERANCE: ± 1%
R6266 = RESISTOR: RES,SMD,0402,56.2KOHM; AGILE_LINK: http://sj-agile9app/Agile/PLMServlet?action=OpenEmailObject&classid=10000&objid=146548997; IPN: J98646-001; Item Num: J98646-001; LIFECYCLE_PHASE: Active; Lead Free Status: No; MFR_LIFECYCLE: Active; Manufacturer: Yageo; Manufacturer Part Num: RT0402BRD0756K2L; Manufaturer: YAGEO CORP; Num Pins: 2; PART_SUBCLASS: RESISTORS; POWER: 1/16W; RoHS Compliant: Yes; TOLERANCE: 1%
R6268 = RESISTOR: RES,1.0 OHMS,1.0%,1/16W, 0402; AGILE_LINK: http://sj-agile9app/Agile/PLMServlet?action=OpenEmailObject&classid=10000&objid=146548997; IPN: A93548-210; Item Num: A93548-210; LIFECYCLE_PHASE: Active; Lead Free Status: No; MFR_LIFECYCLE: Active; Manufacturer: Yageo; Manufacturer Part Num: RC0402FR-071RL; Num Pins: 2; PART_SUBCLASS: RESISTORS; POWER: 1/16W; RoHS Compliant: Yes; TOLERANCE: 1%
R6270 R6271 R6285 R6286 R6289 R6290 R6293 = RESISTOR: RES D,0402,0.00 OHM,5.00%,1/16W; Altera Part No.: P02-14020R; IPN: A93549-001; Item Num: A93549-001; LIFECYCLE_PHASE: Active; Lead Free Status: No; MFR_LIFECYCLE: Active; Manufacturer: Panasonic; Manufacturer Part Num: ERJ-2GE0R00X; Num Pins: 2; PART_SUBCLASS: RESISTORS; POWER: 1/16W; Part Class: RESISTORS; RoHS Compliant: RoHS Compliant; Tolerance: +/-5%
R6276 = CSNL2512FT5L00: RES, CURRENT SENSE, 0.001 OHM, 1%, 3W, +/-50PPM/C, 2512, SMD; IPN: K83723-001; Manufacturer: RIEDON; Manufacturer Part Num: CSR2512C0R001F; WATTAGE: 3W
R6287 R6288 = RESISTOR: RES D,0402,0.00 OHM,5.00%,1/16W; Altera Part No.: P02-14020R; IPN: A93549-001; Item Num: A93549-001; LIFECYCLE_PHASE: Active; Lead Free Status: No; MFR_LIFECYCLE: Active; Manufacturer: Panasonic; Manufacturer Part Num: ERJ-2GE0R00X; Num Pins: 2; PART_SUBCLASS: RESISTORS; POWER: 1/16W; Part Class: RESISTORS; Price: 0; RESISTANCE: 0; RoHS Compliant: RoHS Compliant; Tolerance: +/-5%
ST32 = SHORT
TP1 TP2 TP16 TP17 TP20 TP971 TP1005 = TP,_0.016_,_Thru_Hole
U46 = LTC3543EDCB_0: REGULATOR,20VIN 15A SILENT SW2,15A STEP-DOWN DC/DC; IPN: M21811-001; Item Num: M21811-001; Manufacturer: Analog Devices; Manufacturer Part Num: LTC7151SEV#PBF
U126 = INA219AIDCN: IPN: J64190-001; Item Num: J64190-001
C448 = CAP: CAP - 12PF, 50V, +/-5%, CERAMIC, 0402 SMD; AGILE_LINK: http://sj-agile9app/Agile/PLMServlet?action=OpenEmailObject&classid=10000&objid=257385742; IPN: A36095-043; Item Num: P03-15352R; LIFECYCLE_PHASE: Active; Lead Free Status: Lead Free; MFR_LIFECYCLE: Active; Manufacturer: Panasonic; Manufacturer Part Num: ECJ-0EC1H120J; Num Pins: 2; PART_SUBCLASS: CAPACITORS; RATED_VOLTAGE: 50V; RoHS Compliant: RoHS Compliant; TOLERANCE: +/-5%
C449-C452 = Cap,_NP,_1206: CAP - CER 47UF 10V 20% X5R 1206; IPN: K13655-001; Item Num: P03-17644R; Manufacturer: TDK Electronics; Manufacturer Part Num: C3216X5R1A476M160AB
C453 = Cap,_NP,_0402: CAPC,C0G,0402,100.000PF,50.000V,+/-5%; IPN: A36095-026; Item Num: P03-11677R; Manufacturer: Murata; Manufacturer Part Num: UMK105CG101JV-F; RATED_VOLTAGE: 50V
C455 = Cap,_NP,_0402: CAP - CER, 15PF, 50V, +/-5%, C0G, 0402 SMD; IPN: H83214-001; Item Num: P03-16322R; Manufacturer: Panasonic; Manufacturer Part Num: ECJ-0EC1H150J
C456 C457 C460-C462 = CAP: CAP CER 22UF 10V X5R 0603; AGILE_LINK: http://sj-agile9app/Agile/PLMServlet?action=OpenEmailObject&classid=10000&objid=257560276; IPN: 602433-105; Item Num: P03-18021R; LIFECYCLE_PHASE: Active; Lead Free Status: Not Lead Free; MFR_LIFECYCLE: Active; Manufacturer: Murata; Manufacturer Part Num: GRM188R61A226ME15D; Num Pins: 2; PART_SUBCLASS: CAPACITORS; RATED_VOLTAGE: 10V; RoHS Compliant: RoHS Compliant; TOLERANCE: 20%; Temperature Coefficient: X5R
C458 C459 = CAP: CAP CER 47PF 50V C0G/NP0 0402; AGILE_LINK: http://sj-agile9app/Agile/PLMServlet?action=OpenEmailObject&classid=10000&objid=257560276; IPN: K19455-001; Item Num: P03-17996R; LIFECYCLE_PHASE: Active; Lead Free Status: Not Lead Free; MFR_LIFECYCLE: Active; Manufacturer: Murata; Manufacturer Part Num: GRM1555C1H470FA01D; Num Pins: 2; PART_SUBCLASS: CAPACITORS; RATED_VOLTAGE: 50V; RoHS Compliant: RoHS Compliant; TOLERANCE: 1%; Temperature Coefficient: C0G/NPO
C463-C465 = CAP: CAP CER 22UF 6.3V X6S 0603; AGILE_LINK: http://sj-agile9app/Agile/PLMServlet?action=OpenEmailObject&classid=10000&objid=257560276; IPN: H63299-001; Item Num: P03-17963R; LIFECYCLE_PHASE: Active; Lead Free Status: Lead Free; MFR_LIFECYCLE: Active; Manufacturer: Murata; Manufacturer Part Num: GRM188C80J226ME15D; Num Pins: 2; PART_SUBCLASS: CAPACITORS; RATED_VOLTAGE: 6.3V; RoHS Compliant: RoHS Compliant; TOLERANCE: 20%; Temperature Coefficient: X6S
C466 C467 = CAP: CAP - CER, 10NF, 50V, +/-10%, X7R, 0402 SMD; CAPACITANCE: 0.1uF; Dielectric: X7R; IPN: A36096-100; Item Num: P03-16318R; LIFECYCLE_PHASE: Active; Lead Free Status: Lead Free; Manufacturer: Murata; Manufacturer Part Num: GRM155R71H103KA88D; Num Pins: 2; Part Class: CAPACITORS; RATED_VOLTAGE: 50V; RoHS Compliant: RoHS Compliant; Tolerance: 10%
FB30 FB31 = BEAD_FERRITE_SM: FERRITE BEAD 80 OHM 0805 1LN; IPN: G32678-001; Item Num: P04-17218R; LIFECYCLE_PHASE: Active; MFR_LIFECYCLE: Active; Manufacturer: Laird; Manufacturer Part Num: HI0805R800R-10; Num Pins: 2; PART_SUBCLASS: INDUCTORS; Part Class: Inductors; RoHS Compliant: Yes; Value2: 5A, 10mOhm
R431 R435 R436 R440 = RESISTOR: RES,100K OHMS,1.0%,1/16W,0402; AGILE_LINK: http://sj-agile9app/Agile/PLMServlet?action=OpenEmailObject&classid=10000&objid=146932246; IPN: E86804-001; Item Num: P02-11386R; LIFECYCLE_PHASE: Active; MFR_LIFECYCLE: Active; Manufacturer: Panasonic; Manufacturer Part Num: ERJ-2RKF1003X; Num Pins: 2; PART_SUBCLASS: RESISTORS; POWER: 1/16W; RoHS Compliant: RoHS Compliant; TOLERANCE: +/-1%
R434 R437-R439 = RESISTOR: RES,100K OHMS,1.0%,1/16W,0402; AGILE_LINK: http://sj-agile9app/Agile/PLMServlet?action=OpenEmailObject&classid=10000&objid=146932246; IPN: E86804-001; Item Num: P02-11386R; LIFECYCLE_PHASE: Active; MFR_LIFECYCLE: Active; Manufacturer: Panasonic; Manufacturer Part Num: ERJ-2RKF1003X; Num Pins: 2; PART_SUBCLASS: RESISTORS; POWER: 1/16W; RESISTANCE: 100K; RoHS Compliant: RoHS Compliant; TOLERANCE: +/-1%
R441 = RESISTOR: RES ZERO OHM 1/16W 5% 0402 SMD; Altera Part No.: P02-14020R; IPN: H30887-001; Item Num: P02-14020R; LIFECYCLE_PHASE: Active; Lead Free Status: No; MFR_LIFECYCLE: Active; Manufacturer: Panasonic; Manufacturer Part Num: ERJ-2GE0R00X; Num Pins: 2; PART_SUBCLASS: RESISTORS; POWER: 1/16W; Part Class: RESISTORS; RoHS Compliant: RoHS Compliant; Tolerance: +/-5%
R442 = RESISTOR: RES - 24.9K OHM, 1/16W, 1%, 0402 SMD; Altera Part No.: P02-14020R; IPN: A93548-187; Item Num: P02-15127R; Lead Free Status: No; Manufacturer: Vishay; Manufacturer Part Num: CRCW040224K9FKED; Num Pins: 2; Part Class: RESISTORS; Price: 0; RoHS Compliant: Yes; Tolerance: 1%
R443 = RESISTOR: RES,8.25K OHMS,1.0%,1/16W,0402; IPN: A93548-195; Item Num: P02-11425R; Lead Free Status: No; Manufacturer: Panasonic; Manufacturer Part Num: ERJ-2RKF8251X; Mfr Prt #: ERJ-2RKF8251X; Num Pins: 2; Part Class: Resistors; Price: 0; RoHS Compliant: Yes; Tolerance: 1%
R444 = RESISTOR: RES SMD 4.02KOHM 1% 1/16W 0402; IPN: K15726-001; Item Num: P02-15351R; Lead Free Status: Yes; Manufacturer: Panasonic; Manufacturer Part Num: ERJ-2RKF4021x; Num Pins: 2; Part Class: RESISTORS; RoHS Compliant: Yes; TOLERANCE: 1%
R445 = RESISTOR: RES - 2.61K OHM, 1%,1/10W, 0402 SMD; IPN: G41697-001; Item Num: P02-16710R; Lead Free Status: Yes; Manufacturer: Panasonic; Manufacturer Part Num: ERJ-2RKF2611x; Num Pins: 2; Part Class: RESISTORS; RoHS Compliant: Yes; TOLERANCE: 1%
R446 R447 R785 R786 = RESISTOR: RES,10.0K OHMS,1.0%,1/16W, 0402; AGILE_LINK: http://sj-agile9app/Agile/PLMServlet?action=OpenEmailObject&classid=10000&objid=146548997; IPN: A93548-034; Item Num: P02-11364R; LIFECYCLE_PHASE: Active; Lead Free Status: No; MFR_LIFECYCLE: Active; Manufacturer: Panasonic; Manufacturer Part Num: ERJ-2RKF1002X; Num Pins: 2; PART_SUBCLASS: RESISTORS; POWER: 1/16W; RESISTANCE: 10K; RoHS Compliant: Yes; TOLERANCE: 1%
R448 = RESISTOR: RES SMD 715 OHM 0.1% 1/16W 0402; IPN: A93548-469; Item Num: P02-14329R; Lead Free Status: No; Manufacturer: Vishay; Manufacturer Part Num: CRCW0402715RFKED; Num Pins: 2; Part Class: Resistors; TOLERANCE: 1%
U43 = LTC4625EY: 20VIN, 5A Step-Down DC/DC µModule Regulator; IPN: K21464-001; Item Num: P17-30185R; Manufacturer: Linear; Manufacturer Part Num: LTM4625EY#PBF
U44 U45 = EY1501di-adj: IC,LIN,DFN,ISL80101-AD,VREF; IPN: H38446-001; Item Num: P01-18061R; Manufacturer: Intel/Enpirion; Manufacturer Part Num: ISL80101IRAJZ-T
C1550 = Cap,_NP,_0402: CAP CER 0.1UF 25V 20% X7R 0402; Agile Part Number: P03-17965R; Dielectric: X7R; IPN: K13660-001; Manufacturer: Murata; Manufacturer Part Num: GRM155R71E104KE14D; Package: 0402; Part Number: GRM155R71E104KE14D; RATED_VOLTAGE: 25V; Voltage: 25V
C1816 = CAP: CAP - CER, 1UF, 25V, 10%, X5R, 0402; IPN: H29050-001; Item Num: P03-17662R; Lead Free Status: Yes; Manufacturer: TDK Electronics; Manufacturer Part Num: CGB2A1X5R1E105K033BC; Num Pins: 2; Part Class: CAPACITORS; RoHS Compliant: Yes; Voltage: 25V
C1817 = Cap,_NP,_0402: CAP CER 2.2UF 25V X6S 0402; Agile Part Number: P03-17965R; IPN: M13510-001; Manufacturer: Murata; Manufacturer Part Num: GRM155C81E225ME11D; Package: 0402; Part Number: GRM155C81E225ME11D; Voltage: 25V
C1818 = Cap,_NP,_0402: CAP CER 4.7UF 10V X5R 0402; Agile Part Number: P03-17662R; Dielectric: X5R; IPN: J29703-001; Item Num: P03-17662R; Manufacturer: TDK Electronics; Manufacturer Part Num: CL05A475KP5NRNC; TOLERANCE: ±10%; Voltage: 10V
C1819 C1820 = CAP: CAP, CERAMIC, 2.2UF, 10%, 10VDC, X5R, 0603; IPN: K13568-001; Item Num: P03-15213R; Manufacturer: Murata; Manufacturer Part Num: GRM188R61A225KE34x; RoHS Compliant: RoHS Compliant; Voltage: 10V
C1821 = CAP: CAP CER 330PF 50V X7R 0603; IPN: C21703-001; Item Num: P03-15213R; Manufacturer: PANASONIC; Manufacturer Part Num: ECJ1VC1H331; Part Number: CL05B331KB5VPNC; RoHS Compliant: RoHS Compliant; Voltage: 50V
C1822 = CAP: CAPC,C0G,0402,100.000PF,50.000V,+/-5%; Dielectric: X7R; IPN: A36095-026; IPN No: A36095-026; Item Num: P03-XXXXXR; LIFECYCLE_PHASE: Active; Lead Free Status: Lead Free; Manufacturer: AVX; Manufacturer Part Num: UMK105CG101JV-F; Num Pins: 2; Part Class: CAPACITORS; RATED_VOLTAGE: 50V; RoHS Compliant: RoHS Compliant; Tolerance: 10%
C1823 = CAP: CAP CER 2200pF 25V X7R 0402; IPN: E24654-001; Item Num: P03-15213R; Manufacturer: KEMET; Manufacturer Part Num: C0402C222K3RAC; Part Number: C0402C222K3RAC; RoHS Compliant: RoHS Compliant; Tolerance: 10%; Voltage: 25V
C1824-C1827 = T545X337K016ATE025: IPN: M78371-001
C1829 C1831 C1832 C2011 = Cap,_NP,_1206: CAPC,X6S,1206,22UF,25V,+/- 10%; Agile Part Number: 06593; Dielectric: X5R/X6S; IPN: H65936-001; Manufacturer Part Num: GRM31CC81E226K; Package: 1206; Part Number: GRM31CC81E226K; Structure: MLCC; Voltage: 25V
C2007-C2009 = CAP: CAP CER 0.47UF 6.3V X6S 0402; AGILE_LINK: http://sj-agile9app/Agile/PLMServlet?action=OpenEmailObject&classid=10000&objid=257560276; IPN: D97712-012; IPN No: D97712-012; Item Num: P03-XXXXXR; LIFECYCLE_PHASE: Active; Lead Free Status: Not Lead Free; MFR_LIFECYCLE: Active; Manufacturer: TDK; Manufacturer Part Num: CGB2A3X6S0J474M033BB; Num Pins: 2; PART_SUBCLASS: CAPACITORS; RATED_VOLTAGE: 6.3V; RoHS Compliant: RoHS Compliant; TOLERANCE: 20%; Temperature Coefficient: X6S
C2010 = CAP: CAP CER 0.47UF 6.3V X6S 0402; AGILE_LINK: http://sj-agile9app/Agile/PLMServlet?action=OpenEmailObject&classid=10000&objid=257560276; IPN: D97712-012; IPN No: D97712-012; Item Num: P03-XXXXXR; LIFECYCLE_PHASE: Active; Lead Free Status: Not Lead Free; MFR_LIFECYCLE: Active; Manufacturer: TDK; Manufacturer Part Num: CGB2A3X6S0J474M033BB; Num Pins: 2; PART_SUBCLASS: CAPACITORS; RATED_VOLTAGE: 6.3V; RoHS Compliant: RoHS Compliant; TOLERANCE: 20%; Temperature Coefficient: X6S; Voltage: 6.3V
C2012 = CAP: CAP CER 0.1UF 25V X6S 0402; CAPACITANCE: 0.1uF; Dielectric: X6S; IPN: K19434-001; IPN No: K19434-001; Item Num: P03-XXXXXR; LIFECYCLE_PHASE: Active; Lead Free Status: Lead Free; Manufacturer: Murata; Manufacturer Part Num: GRM155C81E104KA12D; Num Pins: 2; Part Class: CAPACITORS; RATED_VOLTAGE: 25V; RoHS Compliant: RoHS Compliant; Tolerance: 10%; Voltage: 25V
J22 = 95278-101A04LF: IPN: J52509-001
R873 = Resistor,_0402: IPN: K29085-001; Package: 0402
R874-R877 = Resistor,_0402: RES SMD 15K OHM 0.1% 1/10W 0402; IPN: J59798-001; Manufacturer: Panasonic; Manufacturer Part Num: ERA2AEB153X; Package: 0402
R5928 R5930 R5932 R5934 = RESISTOR: RES SMD 499 OHM 0.1% 1/16W 0402; IPN: E59511-001; Item Num: P02-14007R; Lead Free Status: No; Manufacturer: STACKPOLE; Manufacturer Part Num: RNCF0402BTE499R; Num Pins: 2; Part Class: RESISTORS; Part Number: RT0402BRE07499RL; Price: 0; RoHS Compliant: Yes; Tolerance: 0.1%
R5929 R5931 R5933 R5935-R5938 = Resistor,_0402: RES 10K OHM 1/16W 5% 0402 SMD; Agile Part Number: P02-17688R; IPN: A93549-023; Item Num: P02-17688R; Manufacturer: Yageo; Manufacturer Part Num: RC0402JR-0710KL; Part Number: ERJ-2RKF1002X; Power: 1/16W; TOLERANCE: ± 1%
R5939 = RESISTOR: RES SMD 18.7K OHM 1% 1/10W 0402; IPN: K32884-001; Item Num: P02-14007R; Lead Free Status: No; Manufacturer: YAGEO; Manufacturer Part Num: RC0402FR-0718K7L; Num Pins: 2; Part Class: RESISTORS; Price: 0; RoHS Compliant: Yes; Tolerance: 1%
R5940 = RESISTOR: RES SMD 5.11K OHM 1% 1/16W 0402; IPN: G64084-187; Item Num: P02-14007R; Lead Free Status: No; Manufacturer: YAGEO; Manufacturer Part Num: AC0402FR-075K11L; Num Pins: 2; Part Class: RESISTORS; Price: 0; RoHS Compliant: Yes; Tolerance: 1%
R5941 = RESISTOR: RES SMD 3.09K OHM 1% 1/10W 0402; IPN: K15767-001; Item Num: P02-14007R; Lead Free Status: No; Manufacturer: Panasonic Electronic; Manufacturer Part Num: ERJ-2RKF3091X; Num Pins: 2; Part Class: RESISTORS; Price: 0; RoHS Compliant: Yes; Tolerance: 1%
R5942 R6086 = RESISTOR: RES_D,0402,6.49kOHM,1.00%,1/16W; IPN: G21796-165; Item Num: P02-14007R; Lead Free Status: No; Manufacturer: YAGEO CORP; Manufacturer Part Num: RC0402FR-076K49P; Num Pins: 2; Part Class: RESISTORS; Price: 0; RoHS Compliant: Yes; Tolerance: 1%
R5943 R6090 = Resistor,_0402_0: Agile Part Number: 02495; IPN: K29085-001; Manufacturer: Vishay; Manufacturer Part Num: ERJ-2GE0R00X; Package: 0402; Part Number: ERJ-2GE0R00X
R6100 R6105 = Resistor,_0402_0: RES D,0402,0.00 OHM,5.00%,1/16W; Agile Part Number: 02495; IPN: A93549-001; Manufacturer: Vishay; Manufacturer Part Num: ERJ-2GE0R00X; Package: 0402; Part Number: ERJ-2GE0R00X
R6114 R6115 = Resistor,_0402_0: RES D,0402,0.00 OHM,5.00%,1/16W; Agile Part Number: 02495; IPN: A93549-001; Manufacturer Part Num: ERJ-2GE0R00X; Package: 0402; Part Number: ERJ-2GE0R00X
U47 = LTC3888IUHG-1#PBF: IPN: M76261-001

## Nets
5V: C449.1 C450.1 C451.1 C452.1 C453.2 FB30.1 FB31.2 R439.1 U43.C1(VOUT1) U43.D1(VOUT2) U43.D2(VOUT3) U43.E1(VOUT4) U43.E2(VOUT5) ; also on sheet 41 54 63
5V_AGND: C448.1 C454.1 C455.1 R437.2 R441.2 R443.1 U43.B4(SGND)
5V_LDO1: C456.1 FB30.2 R446.1 R785.1 U44.9(VIN1) U44.10(VIN2)
5V_LDO2: C457.1 FB31.1 R447.1 R786.1 U45.9(VIN1) U45.10(VIN2)
5V_PG: R431.1 R432.1 U43.C2(PGOOD) ; also on sheet 46
12V_AUX: C417.2 C418.1 D15.1(C) J16.1(12V) J16.2(12V) J16.3(12V) R404.1 U33.1(S1) U33.2(S2) U33.3(S3) U35.2(IN)
12V_G1: C419.2 C421.1 C422.2 C423.2 C424.2 C428.1 C429.1 C430.1 C431.1 C1817.2 C1824.1 C1825.1 C1826.1 C1827.1 C1829.2 C1831.2 C1832.2 C2011.2 R425.1 U34.1(S1) U34.2(S2) U34.3(S3) U36.6(VOUT) U47.32(VIN) ; also on sheet 9 12 15 18 47 52 53 58
12V_G1_OV_PG: R424.1 U42.6(OUTB) ; also on sheet 46
12V_G1_PG: R407.2 U36.7(~{FAULT}) ; also on sheet 46
12V_G1_UV_PG: R423.1 U42.1(OUTA) ; also on sheet 46
12V_G2: C436.1 C437.1 C438.1 C439.1 C440.1 C441.1 C442.2 C445.2 C446.2 C447.2 C7767.2 C7768.2 C7769.2 C7770.2 C7779.1 R433.1 R440.2 R6268.2 U39.1(S1) U39.2(S2) U39.3(S3) U41.6(VOUT) U42.5(VDD) U43.D5(VIN1) U43.E5(VIN2) U46.4(PVIN) U46.5(PVIN) U46.18(PVIN) U46.19(PVIN) ; also on sheet 45 54 55 57 60 61 63 64
12V_G2_PG: R419.1 U41.7(~{FAULT}) ; also on sheet 46
12V_GROUP1: C425.1 Q12.1(S1) Q12.2(S2) Q12.3(S3) R405.1 R406.1 R411.1 R426.2 U33.5(D) U34.5(D) U35.1(OUT) U35.6(VDD) U36.4(VIN) U37.2(SRC) U37.4(IN)
12V_GROUP2: C427.1 C435.1 Q12.5(D1) R417.1 R418.1 U37.8(OUT) U38.5(D) U39.5(D) U40.1(OUT) U40.6(VDD) U41.4(VIN)
GND: C417.1 C418.2 C419.1 C420.1 C421.2 C422.1 C423.1 C424.1 C425.2 C426.2 C428.2 C429.2 C430.2 C431.2 C432.2 C433.2 C434.1 C435.2 C436.2 C437.2 C438.2 C439.2 C440.2 C441.2 C442.1 C443.1 C444.1 C445.1 C446.1 C447.1 C449.2 C450.2 C451.2 C452.2 C456.2 C457.2 C460.2 C461.2 C462.2 C463.2 C464.2 C465.2 C466.2 C467.2 C1550.1 C1816.1 C1817.1 C1818.1 C1819.2 C1820.2 C1821.2 C1822.1 C1823.2 C1824.2 C1825.2 C1826.2 C1827.2 C1829.1 C1831.1 C1832.1 C2007.1 C2008.1 C2009.1 C2010.1 C2011.1 C7765.2 C7766.2 C7767.1 C7768.1 C7769.1 C7770.1 C7771.2 C7772.2 C7773.2 C7774.2 C7775.2 C7776.2 C7777.1 C7779.2 D15.2 D16.2 J16.4(SENSE1) J16.5(GND) J16.6(SENSE0) J16.7(GND) J16.8(GND) J22.1 J22.3 Q13.2(SOURCE) R404.2 R413.2 R414.2 R416.2 R422.2 R429.1 R430.2 R432.2 R438.2 R441.1 R442.2 R448.2 R449.1 R5936.2 R5939.1 R5940.1 R5941.1 R5942.1 R6086.1 R6100.1 R6267.1 R6270.1 R6272.1 R6287.1 R6288.1 ST32.2 U35.4(GND) U35.7(EP_GND) U36.1(GND) U36.9(GND) U40.4(GND) U40.7(EP_GND) U41.1(GND) U41.9(GND) U42.2(GND) U43.B3(PGND1) U43.C3(PGND2) U43.D3(PGND3) U43.D4(PGND4) U43.E3(PGND6) U44.5(GND) U44.11(EPAD) U45.5(GND) U45.11(EPAD) U46.6(GND) U46.7(GND) U46.8(GND) U46.15(GND) U46.16(GND) U46.17(GND) U46.29(GND) U46.30(GND) U46.31(GND) U46.32(GND) U47.40(VSENSE1+) U47.41(VSENSE1-) U47.53(GND) U126.3(GND) ; also on sheet 9 11 12 13 14 15 17 18 20 21 22 23 24 25 26 28 29 30 31 32 34 35 36 37 38 39 40 41 42 43 44 45 46 47 52 53 54 55 56 57 58 59 60 61 62 63 64 65 66
VCC_SENSE: R6115.1 ; also on sheet 33 52
VDD33_OUT1: C7766.1 R6261.2 R6265.2 R6269.2 U46.20(INTVCC)
VSS_SENSE: R6114.1 ; also on sheet 33 52
1p8V_PRE: C459.2 C463.1 C464.1 C465.1 R445.2 U45.1(VOUT1) U45.2(VOUT2) ; also on sheet 44
1p8V_PRE_PG: R786.2 U45.4(POK)
3p3V: C7777.2 R873.2 R5929.2 R5931.2 R5933.2 R5937.2 R5938.2 R5943.1 R6276.2 R6283.1 R6284.1 R6292.1 U126.4(VSS) ; also on sheet 46 54 55 56 57 58 59 60 61 62 63 64
3p3V_AGND: C7761.2 C7762.1 C7763.1 R6263.2 ST32.1
3p3V_EN: R6265.1 R6267.2 U46.2(RUN) ; also on sheet 46
3p3V_PG: R6261.1 U46.26(PGOOD) ; also on sheet 46
3p3V_STBY: C458.2 C460.1 C461.1 C462.1 R407.1 R419.2 R423.2 R424.2 R444.2 U44.1(VOUT1) U44.2(VOUT2) ; also on sheet 25 39 41 43 44 46 47 62
3p3V_STBY_PG: R785.2 U44.4(POK)
CORE_PMBUS_ALERTn: R516.1 ; also on sheet 43 46
CORE_PMBUS_SCL: R515.1 ; also on sheet 40
CORE_PMBUS_SDA: R514.1 ; also on sheet 40
DAOUT0: C2012.1 R5935.1 U47.11(DAOUT0)
FAULT: R5937.1 R5938.1 R6090.1 U47.18(~{FAULT0}) ; also on sheet 52 53
FPGA_VCC_EN: R877.2 R5943.2 TP16.1 U47.20(RUN0) ; also on sheet 46
FPGA_VCC_PG: R5933.1 TP20.1 U47.13(PGOOD0/CLKOUT) ; also on sheet 46
I2C_INA_SCL: R6283.2 R6286.2 R6289.1 U126.5(SCL)
I2C_INA_SDA: R6284.2 R6285.2 R6290.1 U126.6(SDA)
IN1+_3p3V: C7771.1 C7772.1 C7773.1 C7774.1 C7775.1 C7776.1 L30.2 R6271.1 R6276.1 R6291.1 TP971.1
IREF: C1816.2 R6105.1 U47.33(IREF) U47.43(ISENSE1) U47.44(ISENSE7) U47.47(ISENSE6) U47.48(ISENSE5)
ISENSE0: R5928.2 U47.4(ISENSE0) ; also on sheet 52
ISENSE2: R5932.2 U47.3(ISENSE2) ; also on sheet 53
ISENSE3: R5934.2 U47.52(ISENSE3) ; also on sheet 53
ISENSE4: R5930.2 U47.51(ISENSE4) ; also on sheet 52
ITH0: C1822.2 U47.9(ITH0)
ITHR0: C1823.1 U47.10(ITHR0)
LT4625_INTVCC: C443.2 R431.2 R434.2 R435.2 R436.2 U43.E4(INTVCC)
LTM3888_ALERTn: R516.2 R876.2 TP17.1 U47.17(~{ALERT})
LTM3888_SCL: J22.2 R515.2 R874.2 U47.15(SCL)
LTM3888_SDA: J22.4 R514.2 R875.2 U47.16(SDA)
LTM_SCL: R6286.1 ; also on sheet 54 58
LTM_SDA: R6285.1 ; also on sheet 54 58
PCIE_EP_12V: C433.1 D16.1(C) R412.1 R428.2 U38.1(S1) U38.2(S2) U38.3(S3) U40.2(IN) ; also on sheet 25
PHMD137: R6269.1 R6272.2 U46.28(PHMODE)
POWER_ON: R408.2 R420.2 R429.2 SW5.5 ; also on sheet 46
PWM0: U47.5(PWM0) ; also on sheet 52
PWM2: U47.2(PWM2) ; also on sheet 53
PWM3: U47.1(PWM3) ; also on sheet 53
PWM4: U47.50(PWM4) ; also on sheet 52
SH_CLK: R5931.1 U47.29(SHARE_CLK)
SYNC: R5929.1 U47.14(SYNC)
TSNS0: C1821.1 U47.8(TSNS0/VDR_MON) ; also on sheet 52 53
VFB0: C2012.2 R5935.2 R5936.1 U47.12(VFB0)
N31314586: TP1.1 U43.B5(CLKOUT)
N31314601: TP2.1 U43.A5(CLKIN)
N31314621: C444.2 R433.2 U43.C5(SVIN)
N31314744: R435.1 U43.B2(PHMODE)
N31314754: C448.2 R434.1 U43.A1(COMP)
N31314797: R436.1 R438.1 U43.C4(MODE)
N31314853: R437.1 U43.A4(FREQ)
N31314899: C454.2 U43.A2(TRACK/SS)
N31314949: R440.1 R442.1 U43.A3(RUN)
N31314957: C453.1 C455.2 R439.2 R443.2 U43.B1(FB)
N31415897: Q12.4(G) R409.1
N31415950: C426.1 R409.2 U37.1(GATE)
N31416024: Q13.3(DRAIN) R411.2 U37.5(~{SHDN})
N31416063: C427.2 R416.1 U37.6(VSS)
N31416065: C432.1 R412.2 R414.1 R415.2
N31416086: Q13.1(GATE) R415.1
N32057804: C458.1 R444.1 R448.1 U44.3(VFB)
N32057806: C466.1 U44.6(SS)
N32057886: R446.2 U44.7(EN)
N32121976: C459.1 R445.1 R449.2 U45.3(VFB)
N32121978: C467.1 U45.6(SS)
N32122058: R447.2 U45.7(EN)
N32230321: R828.1 U34.4(G) U36.5(GATE)
N32230341: R406.2 R410.2 U36.3(UV)
N32230392: R410.1 R413.1 U36.2(OV)
N32230759: U33.4(G) U35.3(GATE)
N32232827: U38.4(G) U40.3(GATE)
N32233406: R829.1 U39.4(G) U41.5(GATE)
N32233436: R418.2 R421.2 U41.3(UV)
N32233467: R417.2 R420.1 U41.8(~{SHDN})
N32233496: R421.1 R422.1 U41.2(OV)
N32233958: R426.1 SW5.4
N32406903: R428.1 SW5.6
N32408103: R405.2 R408.1 U36.8(~{SHDN})
N32408438: R425.2 R427.2 U42.3(INA+)
N32408441: R427.1 R430.1 U42.4(INB-)
N37925832: C420.2 R828.2
N37926031: C434.2 R829.2
N38179462: C1550.2 R873.1 R874.1 R875.1 R876.1 R877.1
N40859486: C2007.2 C2008.2 C2009.2 C2010.2 R5928.1 R5930.1 R5932.1 R5934.1 R6105.2
N40859780: C1818.2 U47.31(INTVCC)
N40859787: C1820.1 U47.30(VDD33)
N40859815: C1819.1 U47.28(VDD25)
N40859909: R6100.2 U47.21(RUN1)
N40859911: R5939.2 U47.22(RSET)
N40859913: R5940.2 U47.23(ASEL0)
N40859915: R5941.2 U47.24(ASEL1)
N40859917: R5942.2 U47.25(ILIM0_CFG)
N41030357: R6086.2 U47.27(PWM_CFG)
N41037858: R6090.2 U47.19(~{FAULT1})
N42120524: R6114.2 U47.6(VSENSE0-)
N42120776: R6115.2 U47.7(VSENSE0+)
N42308013: C7761.1 U46.25(TRACK/SS)
N42308046: C7763.2 R6262.2 U46.24(ITH)
N42308122: R6263.1 U46.27(RT)
N42308126: C7764.1 R6264.2 R6266.2 U46.23(FB)
N42308130: C7764.2 R6266.1 R6271.2
N42308290: TP1005.1 U46.1(CLKOUT)
N42308292: R6270.2 R6293.1 U46.22(VOUTM)
N42308326: C7765.1 R6268.1 U46.3(SVIN)
N42308549: L30.1 U46.9(SW1) U46.10(SW2) U46.11(SW3) U46.12(SW4) U46.13(SW5) U46.14(SW6)
N42531609: C7778.1 R6291.2 U126.1(VIN+)
N42531612: C7778.2 R6292.2 U126.2(VIN-)
N42533175: R6287.2 R6289.2 U126.8(A1)
N42533585: R6288.2 R6290.2 U126.7(A0)
N42837491: C7762.2 R6262.1
N43345615: R6264.1 R6293.2

Not connected (* = marked no-connect by the designer): SW5 1* 2* 3*; U35 5(NC)*; U37 3(NC1)* 7(NC2)*; U40 5(NC)*; U44 8(NC)*; U45 8(NC)*; U46 21(M/S)*; U47 26(ILIM1_CFG)* 34(PGOOD1)* 35(VFB1)* 36(DAOUT1)* 37(ITHR1)* 38(ITH1)* 39(TSNS1)* 42(PWM1)* 45(PWM7)* 46(PWM6)* 49(PWM5)*

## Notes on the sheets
sheet 48
- Power - Select Power Input
- H = 1.1mm
  Place on bottom side
- H = 1.0mm
  Place on bottom side
- Vgs(th) = 2.5V/3.7V/4.5V
- PCIe Specs: 12.5A +5%/-8%
- 12V Holding Caps
- Chold = 1160uF for 12_G1
- When 16V,   EN = 1.96V
  When 15V,   EN = 1.84V
  When 14V,   EN = 1.72V
  When 13V,   EN = 1.59V
  When 12V,   EN = 1.47V
  When 11V,   EN = 1.35V
  When 10V,   EN = 1.23V
- When 12V_PCIE = 12V
  EN_12V_G1G2_L = 1.47V
- Vshdn_absmax = 100V
- VGS(th) max = 0.85V
- 12V from PCIe Slot
- H = 1.1mm
  Place on bottom side
- H = 1.0mm
  Place on bottom side
- Vshdn_th = 0.6V/1.2V/2V
- Power On Switch
- Condition   Aux    PCIe    PWR_SW   Start_SEQ
- Bench     Y       N       ON      12V_G1_UV/OV_PG=Y
- Bench     Y       N       OFF      N
- SLOT      Y       Y       X       12V_G1_UV/OV_PG=Y
- SLOT      N       Y       ON       N
- SLOT      N       Y       OFF     12V_G1_UV/OV_PG=N
- Chold = 900uF for 12_G2
- ON
- OFF
- 12V_G1 > 10.46V : OUTA = "1";
  12V_G2 < 13.77V:  OUTB = "1";
  PWR MAX10 get both "1" to start the power seq
sheet 49
- 12V to 5V, 3p3V STBY, 1p8V_PRE
- 5.0V
- VDOmax = 185mV
- VDOmax = 185mV
- Vout = 0.5V x (Rup/Rdn + 1)
- Vout = 0.5V x (Rup/Rdn + 1)
- VINabsmax = -0.3V to 6.5V
- Rup
- VINabsmax = -0.3V to 6.5V
- Rup
- Rdn
- Rdn
- ENth = 0.616V /0.8V / 0.95V
- ENth = 0.616V /0.8V / 0.95V
sheet 50
- MAIN 12V to 3.3V
- Fswitch:
  1.5 MHz
- AGND
- PGND
- I2C ADDRESS IS 0X4E
sheet 51
- VCC Core   Controller
- NOTE: Part Attributes of
  components on this page may not
  match up to the component's
  manufacturer's part number!
- Default Core Voltage = 0.8V @ 121.713A
- Note:
  C1816 Place close to the IREF pin
- Note:
  PWM_CFG: 4+1
  0,2,3,4 Channels Used
- PM Bus ADDR = 47h
- VOUT_SCALE_LOOP = 2 for 0.8V
  Need to Config.
- IOUT_OC_WARN_LIMIT : 44A
- Note:
  Place the Input Cap near to each power stage of LTC7051
- Note: J22 part modified as 2*2 Vertical connector
